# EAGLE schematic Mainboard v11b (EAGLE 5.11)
OC_FARNELL: 2019775

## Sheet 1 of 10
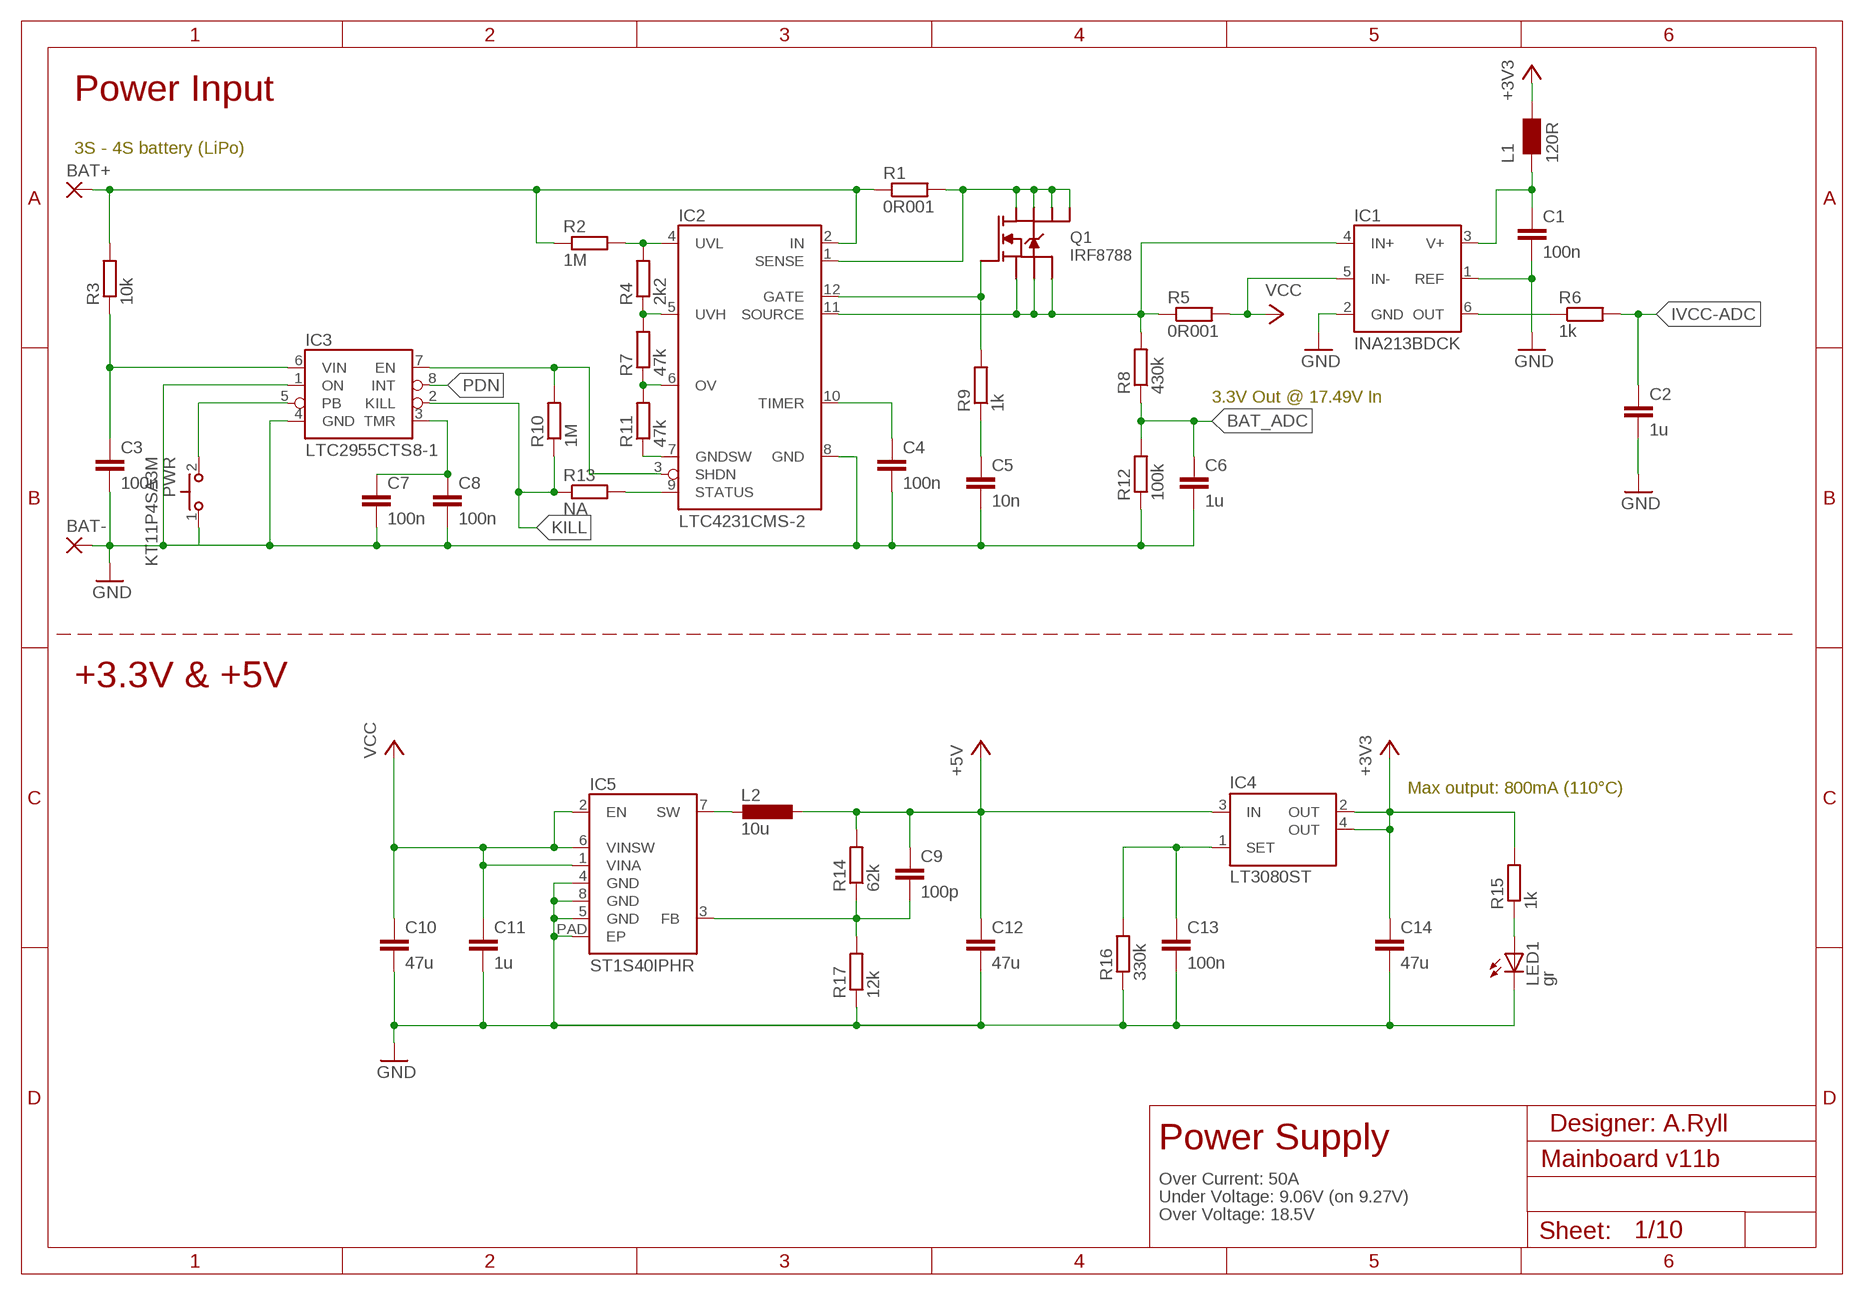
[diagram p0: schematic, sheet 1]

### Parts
BAT+  WIREPAD5,08/3  [5,08/3]
BAT-  WIREPAD5,08/3  [5,08/3]
C1  100n  C-EUC0603  [C0603]
C2  1u  C-EUC0603  [C0603]
C3  100n  C-EUC0603  [C0603]
C4  100n  C-EUC0603  [C0603]
C5  10n  C-EUC0603  [C0603]
C6  1u  C-EUC0603  [C0603]
C7  100n  C-EUC0603  [C0603]
C8  100n  C-EUC0603  [C0603]
C9  100p  C-EUC0603  [C0603]
C10  47u  C-EUC1210  [C1210]
C11  1u  C-EUC0603  [C0603]
C12  47u  C-EUC1210  [C1210]
C13  100n  C-EUC0603  [C0603]
C14  47u  C-EUC1210  [C1210]
IC1  INA213BDCK  INA21XDCK  [SC70-6L]
IC2  LTC4231CMS-2  LTC4231  [MSOP-12]
IC3  LTC2955CTS8-1  LTC2955  [SOT23-8]
IC4  LT3080ST  [SOT223]
IC5  ST1S40IPHR  [HSOP8]
L1  120R  WE-CBF_0603  [0603]
L2  10u  LHCI  [WE-HCI]
LED1  gr  LEDCHIP-LED0603  [CHIP-LED0603]
PWR  KT11P4SA3M  KT11  [KT11]
Q1  IRF8788  NMOS4D  [SOIC8]
R1  0R001  R-EU_R1206  [R1206]
R2  1M  R-EU_R0603  [R0603]
R3  10k  R-EU_R0603  [R0603]
R4  2k2  R-EU_R0603  [R0603]
R5  0R001  R-EU_R1206  [R1206]
R6  1k  R-EU_R0603  [R0603]
R7  47k  R-EU_R0603  [R0603]
R8  430k  R-EU_R0603  [R0603]
R9  1k  R-EU_R0603  [R0603]
R10  1M  R-EU_R0603  [R0603]
R11  47k  R-EU_R0603  [R0603]
R12  100k  R-EU_R0603  [R0603]
R13  NA  R-EU_R0603  [R0603]
R14  62k  R-EU_R0603  [R0603]
R15  1k  R-EU_R0603  [R0603]
R16  330k  R-EU_R0603  [R0603]
R17  12k  R-EU_R0603  [R0603]

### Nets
+3V3: C14.1 IC4.2(OUT) IC4.4(OUT) L1.2 R15.2 ; also sheet 2,3,4,5
+5V: C9.1 C12.1 IC4.3(IN) L2.1 R14.2 ; also sheet 2,3,5,6,7,8,9,10
BAT+: BAT+.P$1(P) IC2.2(IN) R1.1 R2.1 R3.2
BAT_ADC: C6.1 R8.1 R12.2 ; also sheet 2
FB2: C9.2 IC5.3(FB) R14.1 R17.2
GND: BAT-.P$1(P) C1.2 C2.2 C3.2 C4.2 C5.2 C6.2 C7.2 C8.2 C10.2 C11.2 C12.2 C13.2 C14.2 IC1.1(REF) IC1.2(GND) IC2.8(GND) IC3.1(ON) IC3.4(GND) IC5.4(GND) IC5.5(GND) IC5.8(GND) IC5.PAD(EP) LED1.C PWR.1 R12.1 R16.1 R17.1 ; also sheet 2,3,4,5,6,7,8,9,10
IVCC-ADC: C2.1 R6.2 ; also sheet 2
KILL: IC3.2(KILL) R10.1 R13.1 ; also sheet 5
M1-BIN+: IC2.1(SENSE) Q1.5(D1) Q1.6(D2) Q1.7(D3) Q1.8(D4) R1.2
N$6: C13.1 IC4.1(SET) R16.2
N$7: IC2.12(GATE) Q1.4(G) R9.2
N$10: IC2.4(UVL) R2.2 R4.2
N$11: IC2.6(OV) R7.1 R11.2
N$38: IC2.9(STATUS) R13.2
N$47: IC2.5(UVH) R4.1 R7.2
N$48: C5.1 R9.1
N$77: IC2.7(GNDSW) R11.1
N$78: IC2.3(SHDN) IC3.7(EN) R10.2
N$79: IC3.5(PB) PWR.2
N$81: C3.1 IC3.6(VIN) R3.1
N$82: C7.1 C8.1 IC3.3(TMR)
N$84: C4.1 IC2.10(TIMER)
N$107: IC1.6(OUT) R6.1
N$108: C1.1 IC1.3(V+) L1.1
N$120: LED1.A R15.1
PDN: IC3.8(INT) ; also sheet 5
SW2: IC5.7(SW) L2.2
VCC: C10.1 C11.1 IC1.5(IN-) IC5.1(VINA) IC5.2(EN) IC5.6(VINSW) R5.2 ; also sheet 2,3,6,7,8,9,10
VCC-SRC: IC1.4(IN+) IC2.11(SOURCE) Q1.1(S1) Q1.2(S2) Q1.3(S3) R5.1 R8.2

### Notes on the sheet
- Power Input
- 3S - 4S battery (LiPo)
- 3.3V Out @ 17.49V In
- +3.3V & +5V
- Max output: 800mA (110°C)
- Designer: A.Ryll
- Power Supply
- Over Current: 50A
- Under Voltage: 9.06V (on 9.27V)
- Over Voltage: 18.5V

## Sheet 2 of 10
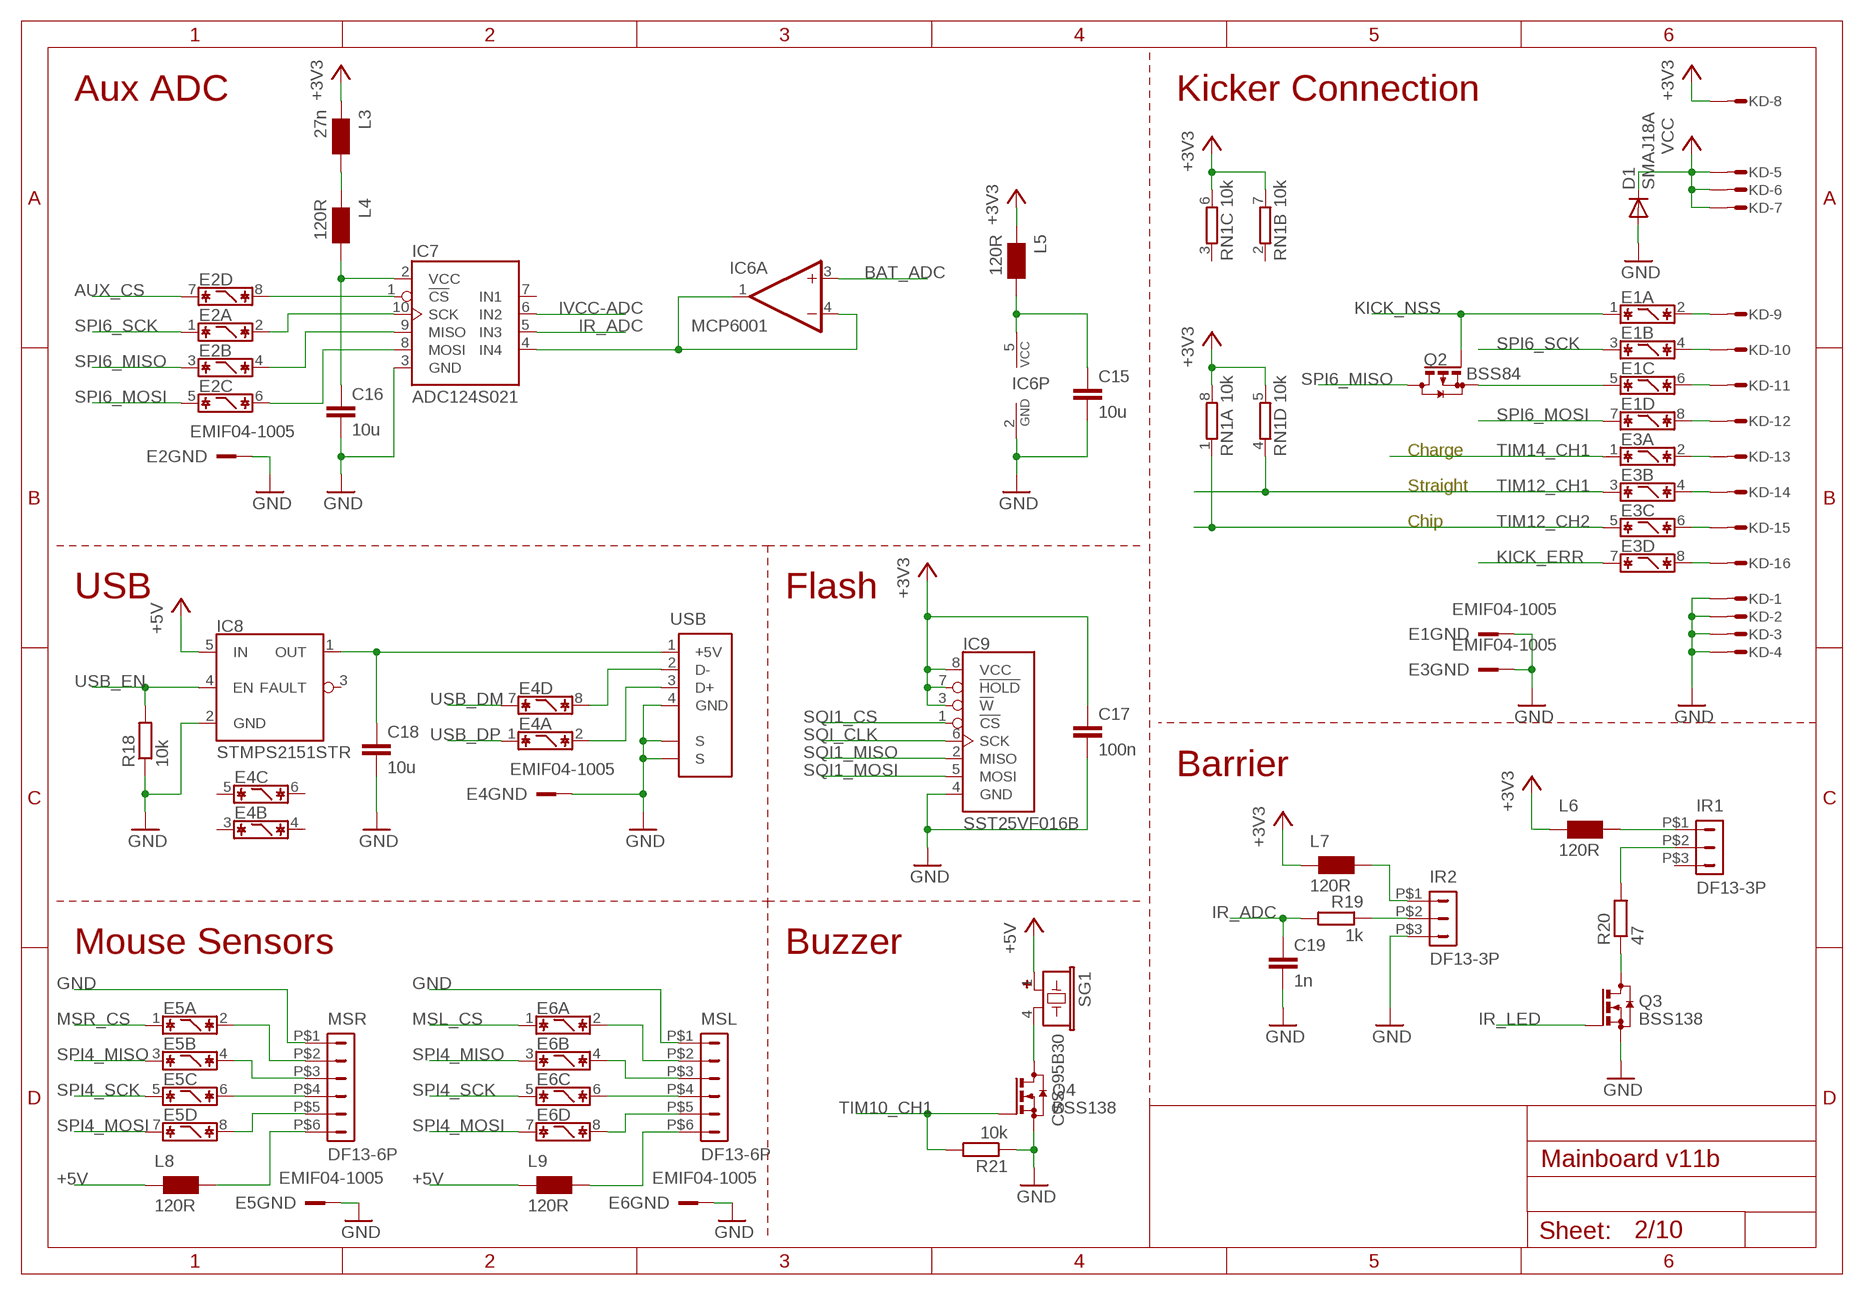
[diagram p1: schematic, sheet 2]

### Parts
C15  10u  C-EUC0603  [C0603]
C16  10u  C-EUC0603  [C0603]
C17  100n  C-EUC0603  [C0603]
C18  10u  C-EUC0603  [C0603]
C19  1n  C-EUC0603  [C0603]
D1  SMAJ18A  DIODE-DO214AC  [DO214AC]
E1  EMIF04-1005  [QFN17X15]
E2  EMIF04-1005  [QFN17X15]
E3  EMIF04-1005  [QFN17X15]
E4  EMIF04-1005  [QFN17X15]
E5  EMIF04-1005  [QFN17X15]
E6  EMIF04-1005  [QFN17X15]
IC6  MCP6001  AD-OP1RT  [SOT23-5]
IC7  ADC124S021  ADC__4S__1  [MSOP10-2]
IC8  STMPS2151STR  [SOT23-5]
IC9  SST25VF016B  FLASHB  [SO08-208]
IR1  DF13-3P  DF13-3P-1.25H  [DF13A-3P-1.25H]
IR2  DF13-3P  DF13-3P-1.25H  [DF13A-3P-1.25H]
KD  MICROMATCH-16SMF  [MMT-F-SMD-16]
L3  27n  WE-MI_0603  [0603]
L4  120R  WE-CBF_0603  [0603]
L5  120R  WE-CBF_0603  [0603]
L6  120R  WE-CBF_0603  [0603]
L7  120R  WE-CBF_0603  [0603]
L8  120R  WE-CBF_0603  [0603]
L9  120R  WE-CBF_0603  [0603]
MSL  DF13-6P  DF13-6P-1.25H  [DF13A-6P-1.25H]
MSR  DF13-6P  DF13-6P-1.25H  [DF13A-6P-1.25H]
Q2  BSS84  [SOT23]
Q3  BSS138  BSS123  [SOT23]
Q4  BSS138  BSS123  [SOT23]
R18  10k  R-EU_R0603  [R0603]
R19  1k  R-EU_R0603  [R0603]
R20  47  R-EU_R1206  [R1206]
R21  10k  R-EU_R0603  [R0603]
RN1  10k  4R-NEXB28V  [EXB28V]
SG1  CSS-95B30  BUZZER  [CSS-95B30]
USB  USBATE  [USBA-TE]

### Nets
+3V3: C17.1 IC9.3(!W) IC9.7(!HOLD) IC9.8(VCC) KD.8 L3.1 L5.1 L6.1 L7.1 RN1.5 RN1.6 RN1.7 RN1.8 ; also sheet 1,3,4,5
+5V: IC8.5(IN) L8.1 L9.1 SG1.1(+) ; also sheet 1,3,5,6,7,8,9,10
AUX_CS: E2.7 ; also sheet 5
BAT_ADC: IC6.3(A:+IN) ; also sheet 1
GND: C15.2 C16.2 C17.2 C18.2 C19.2 D1.A E1.GND(GND:KL) E2.GND(GND:KL) E3.GND(GND:KL) E4.GND(GND:KL) E5.GND(GND:KL) E6.GND(GND:KL) IC6.2(P:GND) IC7.3(GND) IC8.2(GND) IC9.4(GND) IR2.P$3 KD.1 KD.2 KD.3 KD.4 MSL.P$1 MSR.P$1 Q3.2(S) Q4.2(S) R18.1 R21.1 USB.4(GND) USB.MNT1(S) USB.MNT2(S) ; also sheet 1,3,4,5,6,7,8,9,10
IR_ADC: C19.1 IC7.5(IN3) R19.2
IR_LED: Q3.1(G) ; also sheet 5
IVCC-ADC: IC7.6(IN2) ; also sheet 1
KICK_ERR: E3.7 ; also sheet 5
KICK_NSS: E1.1 Q2.1(G) ; also sheet 5
MSL_CS: E6.1 ; also sheet 5
MSR_CS: E5.1 ; also sheet 5
N$3: IR2.P$2 R19.1
N$28: Q4.3(D) SG1.4(-)
N$43: L3.2 L4.1
N$45: IR2.P$1 L7.2
N$53: Q3.3(D) R20.1
N$54: IR1.P$2 R20.2
N$57: E5.2 MSR.P$2
N$63: E5.4 MSR.P$3
N$68: E5.6 MSR.P$4
N$69: C16.1 IC7.2(VCC) L4.2
N$70: E2.8 IC7.1(!CS)
N$71: E5.8 MSR.P$5
N$72: E2.2 IC7.10(SCK)
N$73: E2.6 IC7.8(MOSI)
N$74: E2.4 IC7.9(MISO)
N$75: IC6.1(A:OUT) IC6.4(A:-IN) IC7.4(IN4)
N$76: C15.1 IC6.5(P:VCC) L5.2
N$93: E4.8 USB.2(D-)
N$96: IR1.P$1 L6.2
N$101: E4.2 USB.3(D+)
N$104: E1.5 Q2.2(S)
N$111: L8.2 MSR.P$6
N$117: E6.2 MSL.P$2
N$136: E6.4 MSL.P$3
N$137: E6.6 MSL.P$4
N$138: E6.8 MSL.P$5
N$139: L9.2 MSL.P$6
N$192: E1.2 KD.9
N$201: E1.4 KD.10
N$202: E1.6 KD.11
N$203: E1.8 KD.12
N$204: E3.2 KD.13
N$205: E3.4 KD.14
N$206: E3.6 KD.15
N$214: E3.8 KD.16
SPI4_MISO: E5.3 E6.3 ; also sheet 3,5
SPI4_MOSI: E5.7 E6.7 ; also sheet 3,5
SPI4_SCK: E5.5 E6.5 ; also sheet 3,5
SPI6_MISO: E2.3 Q2.3(D) ; also sheet 3,5
SPI6_MOSI: E1.7 E2.5 ; also sheet 3,5
SPI6_SCK: E1.3 E2.1 ; also sheet 3,5
SQI1_CS: IC9.1(!CS) ; also sheet 5
SQI1_MISO: IC9.2(MISO) ; also sheet 5
SQI1_MOSI: IC9.5(MOSI) ; also sheet 5
SQI_CLK: IC9.6(SCK) ; also sheet 5
TIM10_CH1: Q4.1(G) R21.2 ; also sheet 5
TIM12_CH1: E3.3 RN1.4 ; also sheet 5
TIM12_CH2: E3.5 RN1.1 ; also sheet 5
TIM14_CH1: E3.1 ; also sheet 5
USB-5V: C18.1 IC8.1(OUT) USB.1(+5V)
USB_DM: E4.7 ; also sheet 5
USB_DP: E4.1 ; also sheet 5
USB_EN: IC8.4(EN) R18.2 ; also sheet 5
VCC: D1.C KD.5 KD.6 KD.7 ; also sheet 1,3,6,7,8,9,10
Unconnected: E4.3 E4.4 E4.5 E4.6 IC7.7(IN1) IC8.3(FAULT) IR1.P$3 RN1.2 RN1.3

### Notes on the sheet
- Aux ADC | Kicker Connection
- Charge
- Straight
- Chip
- USB | Flash
- Barrier
- Mouse Sensors | Buzzer

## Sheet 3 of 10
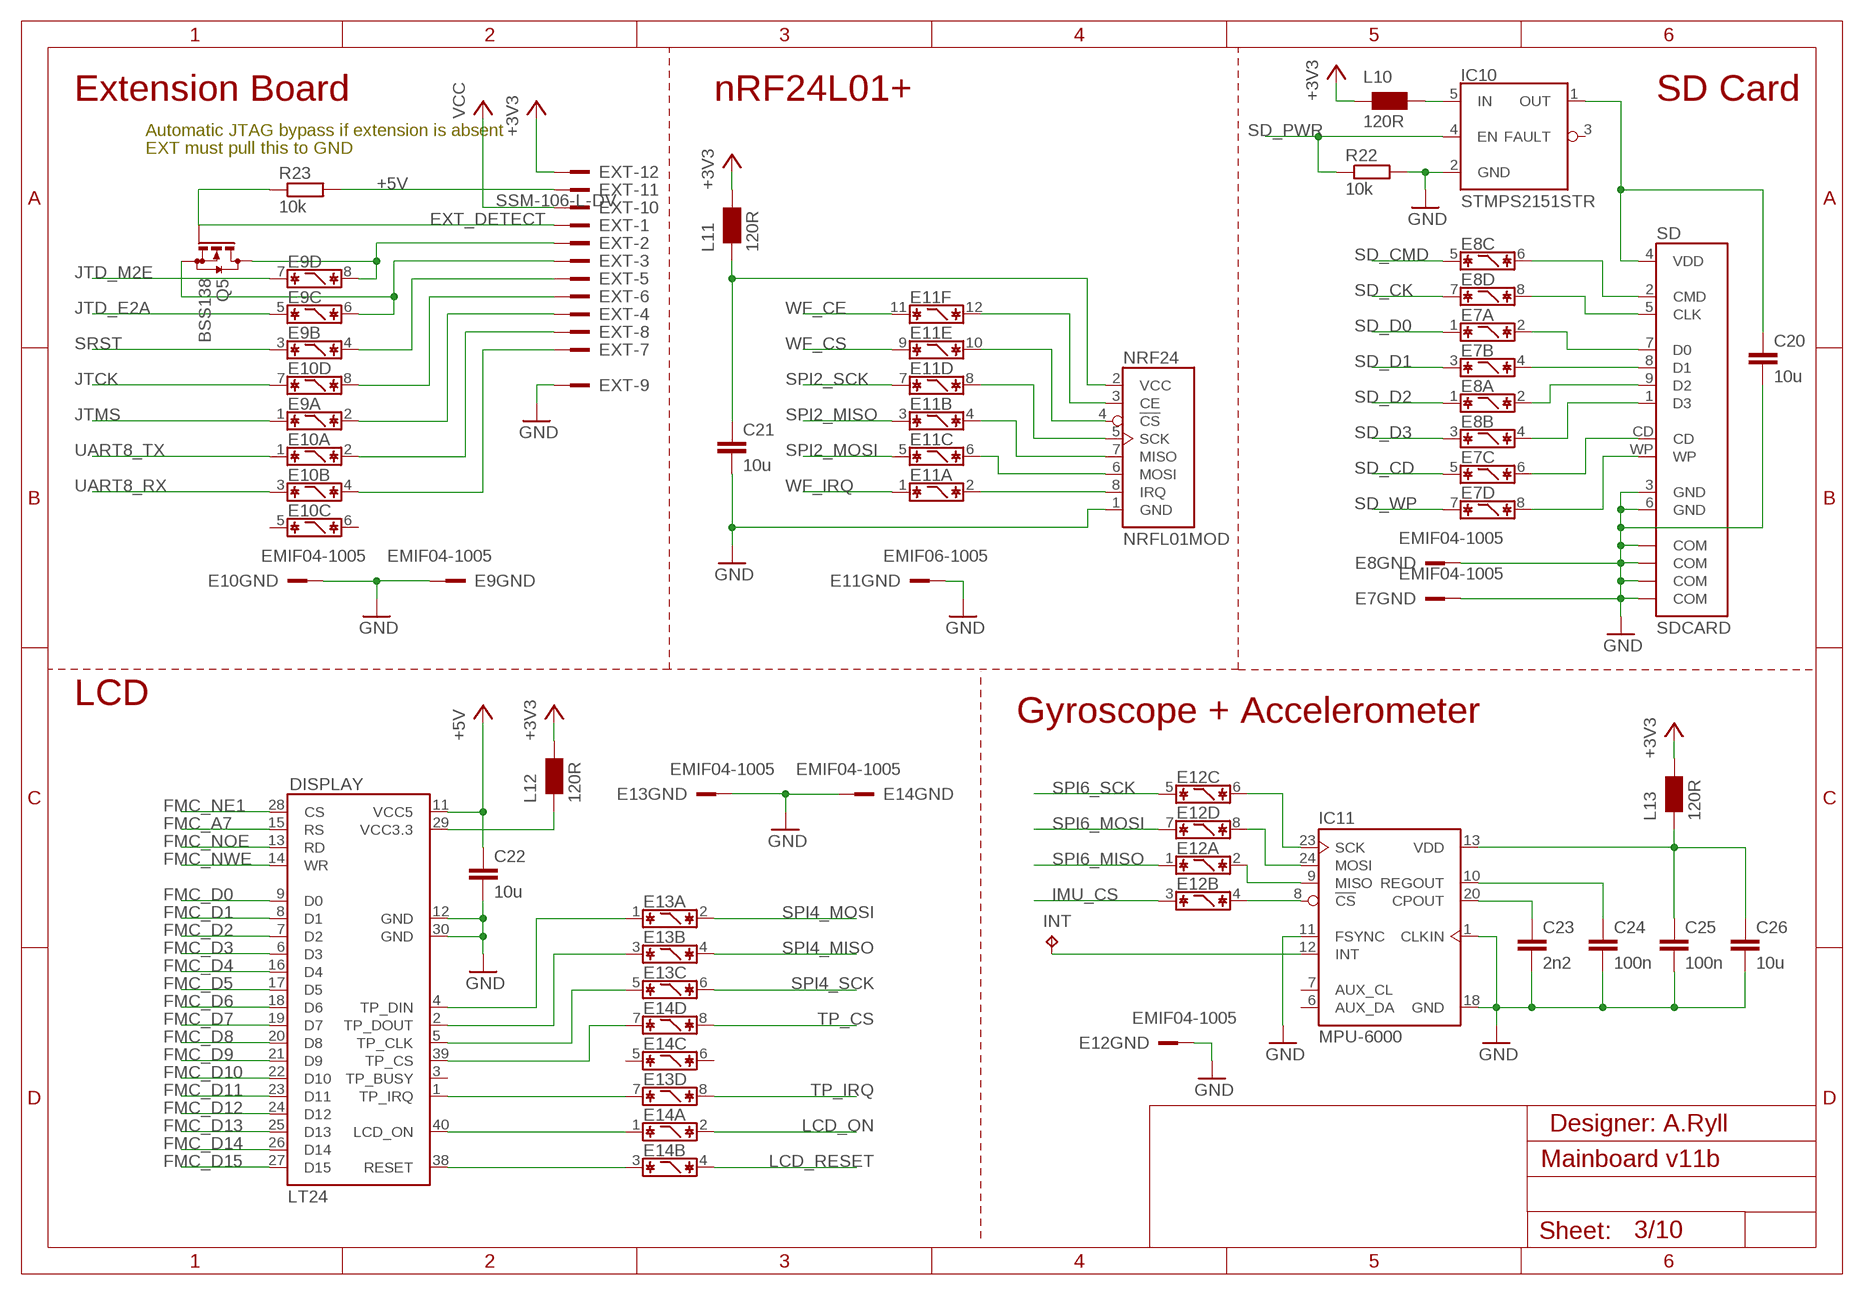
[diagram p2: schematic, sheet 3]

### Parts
C20  10u  C-EUC0603  [C0603]
C21  10u  C-EUC0603  [C0603]
C22  10u  C-EUC0603  [C0603]
C23  2n2  C-EUC0603  [C0603]
C24  100n  C-EUC0603  [C0603]
C25  100n  C-EUC0603  [C0603]
C26  10u  C-EUC0603  [C0603]
DISPLAY  LT24  [LT24]
E7  EMIF04-1005  [QFN17X15]
E8  EMIF04-1005  [QFN17X15]
E9  EMIF04-1005  [QFN17X15]
E10  EMIF04-1005  [QFN17X15]
E11  EMIF06-1005  [QFN25X15]
E12  EMIF04-1005  [QFN17X15]
E13  EMIF04-1005  [QFN17X15]
E14  EMIF04-1005  [QFN17X15]
EXT  SSM-106-L-DV  XSM-106-DV  [XSM-106-DV]
IC10  STMPS2151STR  [SOT23-5]
IC11  MPU-6000  [QFN4X4-24]
INT  TPTP08R  [TP08R]
L10  120R  WE-CBF_0603  [0603]
L11  120R  WE-CBF_0603  [0603]
L12  120R  WE-CBF_0603  [0603]
L13  120R  WE-CBF_0603  [0603]
NRF24  NRFL01MOD  NRFL01MODP  [NRF24L01SLR]
Q5  BSS138  BSS123  [SOT23]
R22  10k  R-EU_R0603  [R0603]
R23  10k  R-EU_R0603  [R0603]
SD  SDCARD  [SDCARD]

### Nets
+3V3: EXT.12 L10.1 L11.2 L12.2 L13.2 ; also sheet 1,2,4,5
+5V: C22.1 DISPLAY.11(VCC5) EXT.11 R23.2 ; also sheet 1,2,5,6,7,8,9,10
EXT_DETECT: EXT.1 Q5.1(G) R23.1
FMC_A7: DISPLAY.15(RS) ; also sheet 5
FMC_D0: DISPLAY.9(D0) ; also sheet 5
FMC_D1: DISPLAY.8(D1) ; also sheet 5
FMC_D2: DISPLAY.7(D2) ; also sheet 5
FMC_D3: DISPLAY.6(D3) ; also sheet 5
FMC_D4: DISPLAY.16(D4) ; also sheet 5
FMC_D5: DISPLAY.17(D5) ; also sheet 5
FMC_D6: DISPLAY.18(D6) ; also sheet 5
FMC_D7: DISPLAY.19(D7) ; also sheet 5
FMC_D8: DISPLAY.20(D8) ; also sheet 5
FMC_D9: DISPLAY.21(D9) ; also sheet 5
FMC_D10: DISPLAY.22(D10) ; also sheet 5
FMC_D11: DISPLAY.23(D11) ; also sheet 5
FMC_D12: DISPLAY.24(D12) ; also sheet 5
FMC_D13: DISPLAY.25(D13) ; also sheet 5
FMC_D14: DISPLAY.26(D14) ; also sheet 5
FMC_D15: DISPLAY.27(D15) ; also sheet 5
FMC_NE1: DISPLAY.28(CS) ; also sheet 5
FMC_NOE: DISPLAY.13(RD) ; also sheet 5
FMC_NWE: DISPLAY.14(WR) ; also sheet 5
GND: C20.2 C21.2 C22.2 C23.2 C24.2 C25.2 C26.2 DISPLAY.12(GND) DISPLAY.30(GND) E7.GND(GND:KL) E8.GND(GND:KL) E9.GND(GND:KL) E10.GND(GND:KL) E11.GND(GND:KL) E12.GND(GND:KL) E13.GND(GND:KL) E14.GND(GND:KL) EXT.9 IC10.2(GND) IC11.1(CLKIN) IC11.11(FSYNC) IC11.18(GND) NRF24.1(GND) R22.2 SD.3(GND) SD.6(GND) SD.COM1(COM) SD.COM2(COM) SD.COM3(COM) SD.COM4(COM) ; also sheet 1,2,4,5,6,7,8,9,10
IMU_CS: E12.3 ; also sheet 5
JTCK: E10.7 ; also sheet 4,5
JTD_E2A: E9.5 ; also sheet 4
JTD_M2E: E9.7 ; also sheet 5
JTMS: E9.1 ; also sheet 4,5
LCD_ON: E14.2 ; also sheet 5
LCD_RESET: E14.4 ; also sheet 5
N$1: IC10.5(IN) L10.2
N$4: C20.1 IC10.1(OUT) SD.4(VDD)
N$15: IC11.12(INT) INT.TP
N$17: E8.6 SD.2(CMD)
N$21: E8.8 SD.5(CLK)
N$23: E7.2 SD.7(D0)
N$24: E7.4 SD.8(D1)
N$26: C23.1 IC11.20(CPOUT)
N$27: C25.1 C26.1 IC11.13(VDD) L13.1
N$35: E8.2 SD.9(D2)
N$36: E8.4 SD.1(D3)
N$37: E7.6 SD.CD
N$39: E7.8 SD.WP
N$46: E9.8 EXT.2 Q5.3(D)
N$80: E9.6 EXT.3 Q5.2(S)
N$83: E9.4 EXT.5
N$85: E10.8 EXT.6
N$86: E9.2 EXT.4
N$87: E10.2 EXT.8
N$88: E10.4 EXT.7
N$95: DISPLAY.29(VCC3.3) L12.1
N$97: DISPLAY.4(TP_DIN) E13.1
N$98: DISPLAY.2(TP_DOUT) E13.3
N$99: DISPLAY.5(TP_CLK) E13.5
N$100: DISPLAY.39(TP_CS) E14.7
N$102: C21.1 L11.1 NRF24.2(VCC)
N$103: E11.2 NRF24.8(IRQ)
N$109: C24.1 IC11.10(REGOUT)
N$112: E11.4 NRF24.7(MISO)
N$113: E11.6 NRF24.6(MOSI)
N$114: E11.8 NRF24.5(SCK)
N$115: E11.10 NRF24.4(!CS)
N$116: E11.12 NRF24.3(CE)
N$118: E12.6 IC11.23(SCK)
N$119: E12.8 IC11.24(MOSI)
N$121: E12.2 IC11.9(MISO)
N$122: E12.4 IC11.8(!CS)
N$124: DISPLAY.1(TP_IRQ) E13.7
N$125: DISPLAY.40(LCD_ON) E14.1
N$126: DISPLAY.38(RESET) E14.3
SD_CD: E7.5 ; also sheet 5
SD_CK: E8.7 ; also sheet 5
SD_CMD: E8.5 ; also sheet 5
SD_D0: E7.1 ; also sheet 5
SD_D1: E7.3 ; also sheet 5
SD_D2: E8.1 ; also sheet 5
SD_D3: E8.3 ; also sheet 5
SD_PWR: IC10.4(EN) R22.1 ; also sheet 5
SD_WP: E7.7 ; also sheet 5
SPI2_MISO: E11.3 ; also sheet 5
SPI2_MOSI: E11.5 ; also sheet 5
SPI2_SCK: E11.7 ; also sheet 5
SPI4_MISO: E13.4 ; also sheet 2,5
SPI4_MOSI: E13.2 ; also sheet 2,5
SPI4_SCK: E13.6 ; also sheet 2,5
SPI6_MISO: E12.1 ; also sheet 2,5
SPI6_MOSI: E12.7 ; also sheet 2,5
SPI6_SCK: E12.5 ; also sheet 2,5
SRST: E9.3 ; also sheet 4,5
TP_CS: E14.8 ; also sheet 5
TP_IRQ: E13.8 ; also sheet 5
UART8_RX: E10.3 ; also sheet 5
UART8_TX: E10.1 ; also sheet 5
VCC: EXT.10 ; also sheet 1,2,6,7,8,9,10
WF_CE: E11.11 ; also sheet 5
WF_CS: E11.9 ; also sheet 5
WF_IRQ: E11.1 ; also sheet 5
Unconnected: DISPLAY.3(TP_BUSY) E10.5 E10.6 E14.5 E14.6 IC10.3(FAULT) IC11.6(AUX_DA) IC11.7(AUX_CL)

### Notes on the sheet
- Extension Board | nRF24L01+ | SD Card
- Automatic JTAG bypass if extension is absent
- EXT must pull this to GND
- LCD
- Gyroscope + Accelerometer
- Designer: A.Ryll

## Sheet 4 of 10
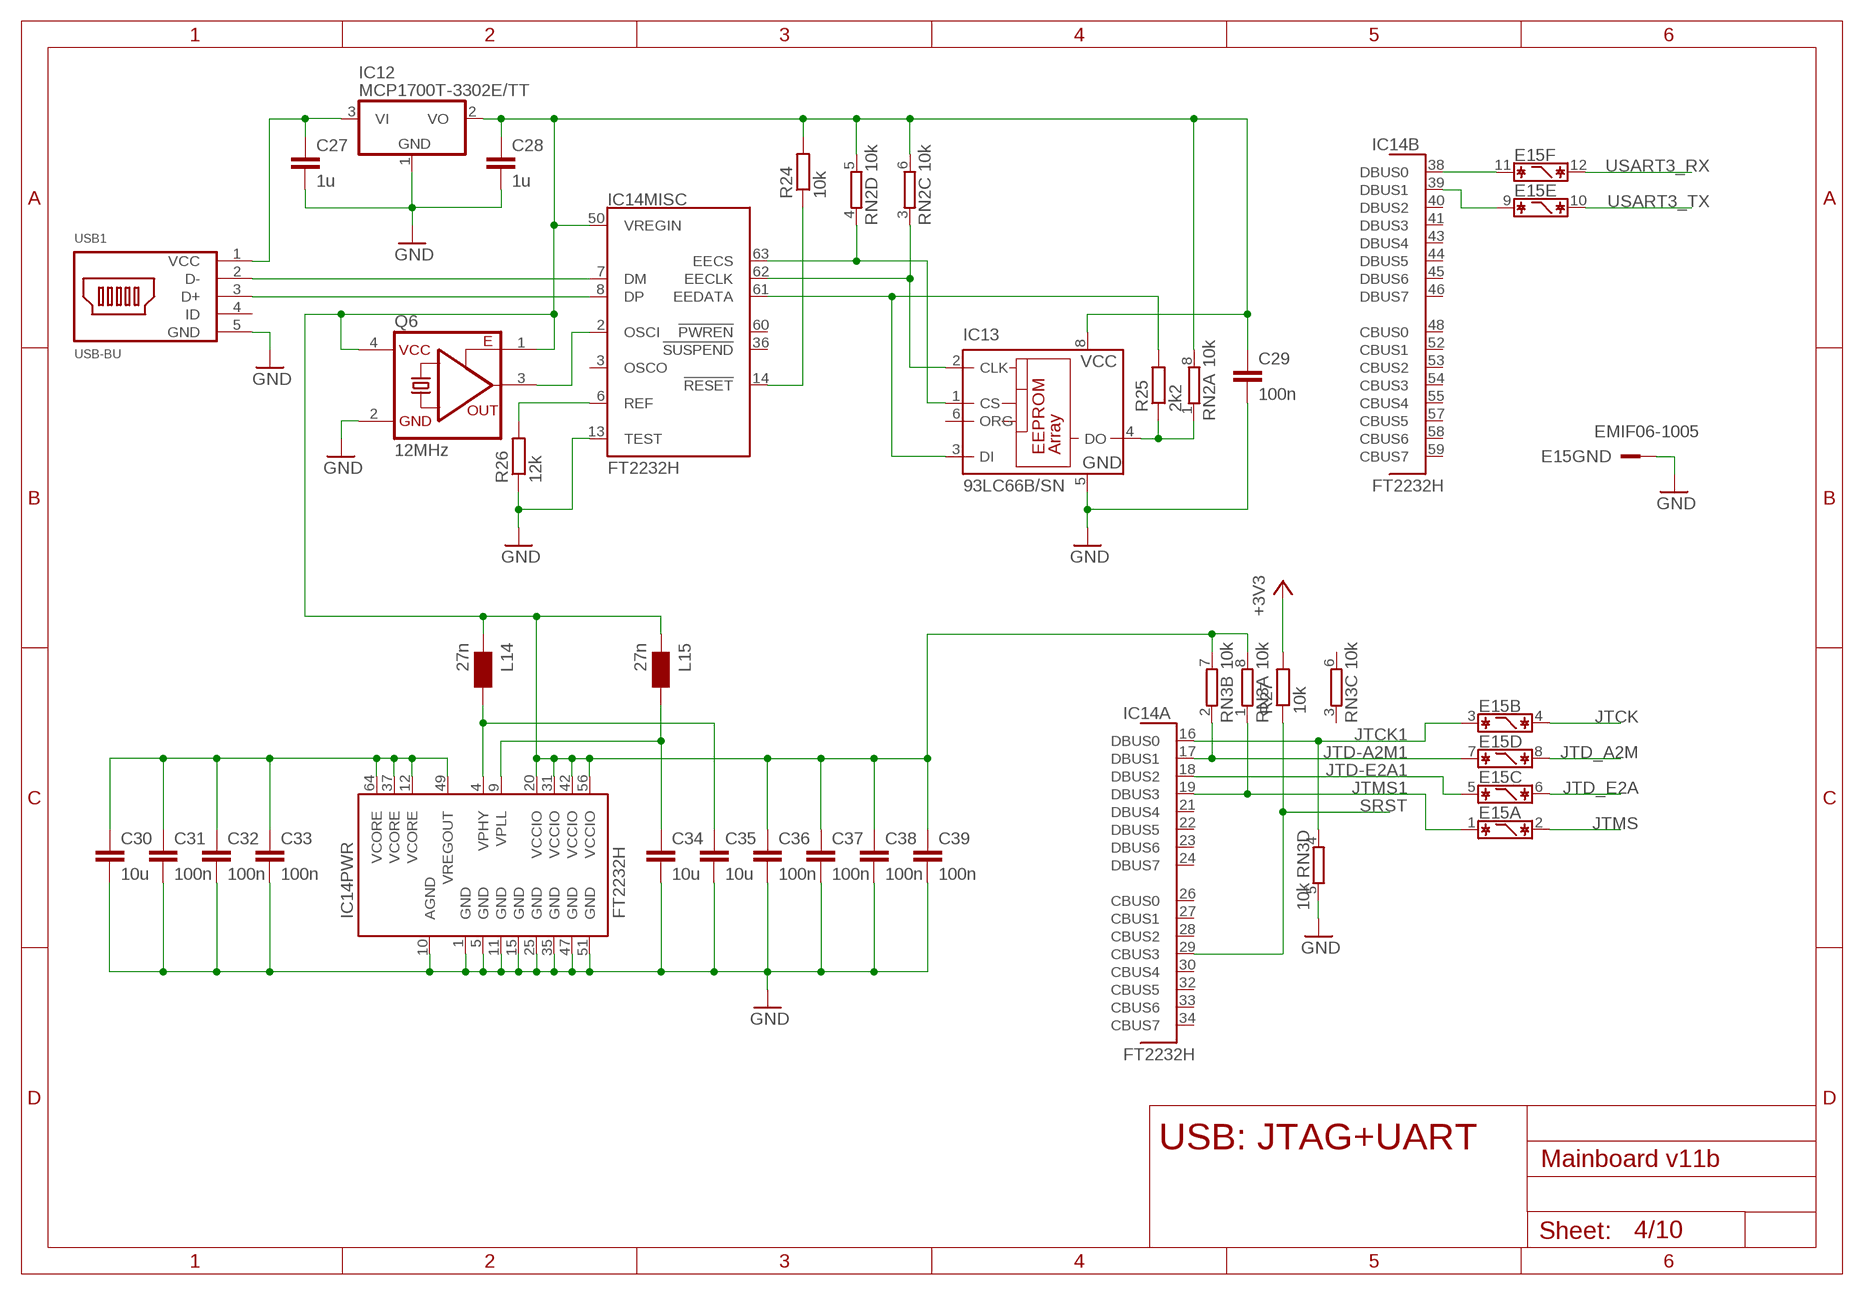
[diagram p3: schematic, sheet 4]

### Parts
C27  1u  C-EUC0603  [C0603]
C28  1u  C-EUC0603  [C0603]
C29  100n  C-EUC0603  [C0603]
C30  10u  C-EUC0603  [C0603]
C31  100n  C-EUC0603  [C0603]
C32  100n  C-EUC0603  [C0603]
C33  100n  C-EUC0603  [C0603]
C34  10u  C-EUC0603  [C0603]
C35  10u  C-EUC0603  [C0603]
C36  100n  C-EUC0603  [C0603]
C37  100n  C-EUC0603  [C0603]
C38  100n  C-EUC0603  [C0603]
C39  100n  C-EUC0603  [C0603]
E15  EMIF06-1005  [QFN25X15]
IC12  MCP1700T-3302E/TT  MCP1703CB  [SOT23]
IC13  93LC66B/SN  93LC66SN  [SO-08]
IC14  FT2232H  [LQFP64-ST]
L14  27n  WE-MI_0603  [0603]
L15  27n  WE-MI_0603  [0603]
Q6  12MHz  OSCI8W  [CRYSTAL-8W]
R24  10k  R-EU_R0603  [R0603]
R25  2k2  R-EU_R0603  [R0603]
R26  12k  R-EU_R0603  [R0603]
R27  10k  R-EU_R0603  [R0603]
RN2  10k  4R-NEXB28V  [EXB28V]
RN3  10k  4R-NEXB28V  [EXB28V]
USB1  USB-BU  [USB-BMICRO]

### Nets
+3V3: R27.2 ; also sheet 1,2,3,5
FT_3V3: C28.1 C29.1 C36.1 C37.1 C38.1 C39.1 IC12.2(VO) IC13.8(VCC) IC14.20(PWR:VCCIO) IC14.31(PWR:VCCIO) IC14.42(PWR:VCCIO) IC14.50(MISC:VREGIN) IC14.56(PWR:VCCIO) L14.1 L15.1 Q6.1(OE) Q6.4(VCC) R24.2 RN2.5 RN2.6 RN2.8 RN3.7 RN3.8
GND: C27.2 C28.2 C29.2 C30.2 C31.2 C32.2 C33.2 C34.2 C35.2 C36.2 C37.2 C38.2 C39.2 E15.GND(GND:KL) IC12.1(GND) IC13.5(GND) IC14.1(PWR:GND) IC14.5(PWR:GND) IC14.10(PWR:AGND) IC14.11(PWR:GND) IC14.13(MISC:TEST) IC14.15(PWR:GND) IC14.25(PWR:GND) IC14.35(PWR:GND) IC14.47(PWR:GND) IC14.51(PWR:GND) Q6.2(GND) R26.1 RN3.5 USB1.5(GND) ; also sheet 1,2,3,5,6,7,8,9,10
JTCK: E15.4 ; also sheet 3,5
JTCK1: E15.3 IC14.16(A:DBUS0) RN3.4
JTD-A2M1: E15.7 IC14.17(A:DBUS1) RN3.2
JTD-E2A1: E15.5 IC14.18(A:DBUS2)
JTD_A2M: E15.8 ; also sheet 5
JTD_E2A: E15.6 ; also sheet 3
JTMS: E15.2 ; also sheet 3,5
JTMS1: E15.1 IC14.19(A:DBUS3) RN3.1
N$41: C30.1 C31.1 C32.1 C33.1 IC14.12(PWR:VCORE) IC14.37(PWR:VCORE) IC14.49(PWR:VREGOUT) IC14.64(PWR:VCORE)
N$42: C27.1 IC12.3(VI) USB1.1(VCC)
N$44: IC14.7(MISC:DM) USB1.2(D-)
N$49: IC14.8(MISC:DP) USB1.3(D+)
N$51: IC14.6(MISC:REF) R26.2
N$52: C34.1 IC14.9(PWR:VPLL) L15.2
N$55: IC14.14(MISC:!RESET) R24.1
N$56: C35.1 IC14.4(PWR:VPHY) L14.2
N$58: IC14.2(MISC:OSCI) Q6.3(FO)
N$59: IC13.4(DO) R25.1 RN2.1
N$60: IC13.3(DI) IC14.61(MISC:EEDATA) R25.2
N$61: IC13.2(CLK) IC14.62(MISC:EECLK) RN2.3
N$62: IC13.1(CS) IC14.63(MISC:EECS) RN2.4
N$64: E15.11 IC14.38(B:DBUS0)
N$66: E15.9 IC14.39(B:DBUS1)
SRST: IC14.29(A:CBUS3) R27.1 ; also sheet 3,5
USART3_RX: E15.12 ; also sheet 5
USART3_TX: E15.10 ; also sheet 5
Unconnected: IC13.6(ORG) IC13.7(NU) IC14.3(MISC:OSCO) IC14.21(A:DBUS4) IC14.22(A:DBUS5) IC14.23(A:DBUS6) IC14.24(A:DBUS7) IC14.26(A:CBUS0) IC14.27(A:CBUS1) IC14.28(A:CBUS2) IC14.30(A:CBUS4) IC14.32(A:CBUS5) IC14.33(A:CBUS6) IC14.34(A:CBUS7) IC14.36(MISC:!SUSPEND) IC14.40(B:DBUS2) IC14.41(B:DBUS3) IC14.43(B:DBUS4) IC14.44(B:DBUS5) IC14.45(B:DBUS6) IC14.46(B:DBUS7) IC14.48(B:CBUS0) IC14.52(B:CBUS1) IC14.53(B:CBUS2) IC14.54(B:CBUS3) IC14.55(B:CBUS4) IC14.57(B:CBUS5) IC14.58(B:CBUS6) IC14.59(B:CBUS7) IC14.60(MISC:!PWREN) RN2.2 RN2.7 RN3.3 RN3.6 USB1.4(ID)

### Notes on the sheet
- USB: JTAG+UART

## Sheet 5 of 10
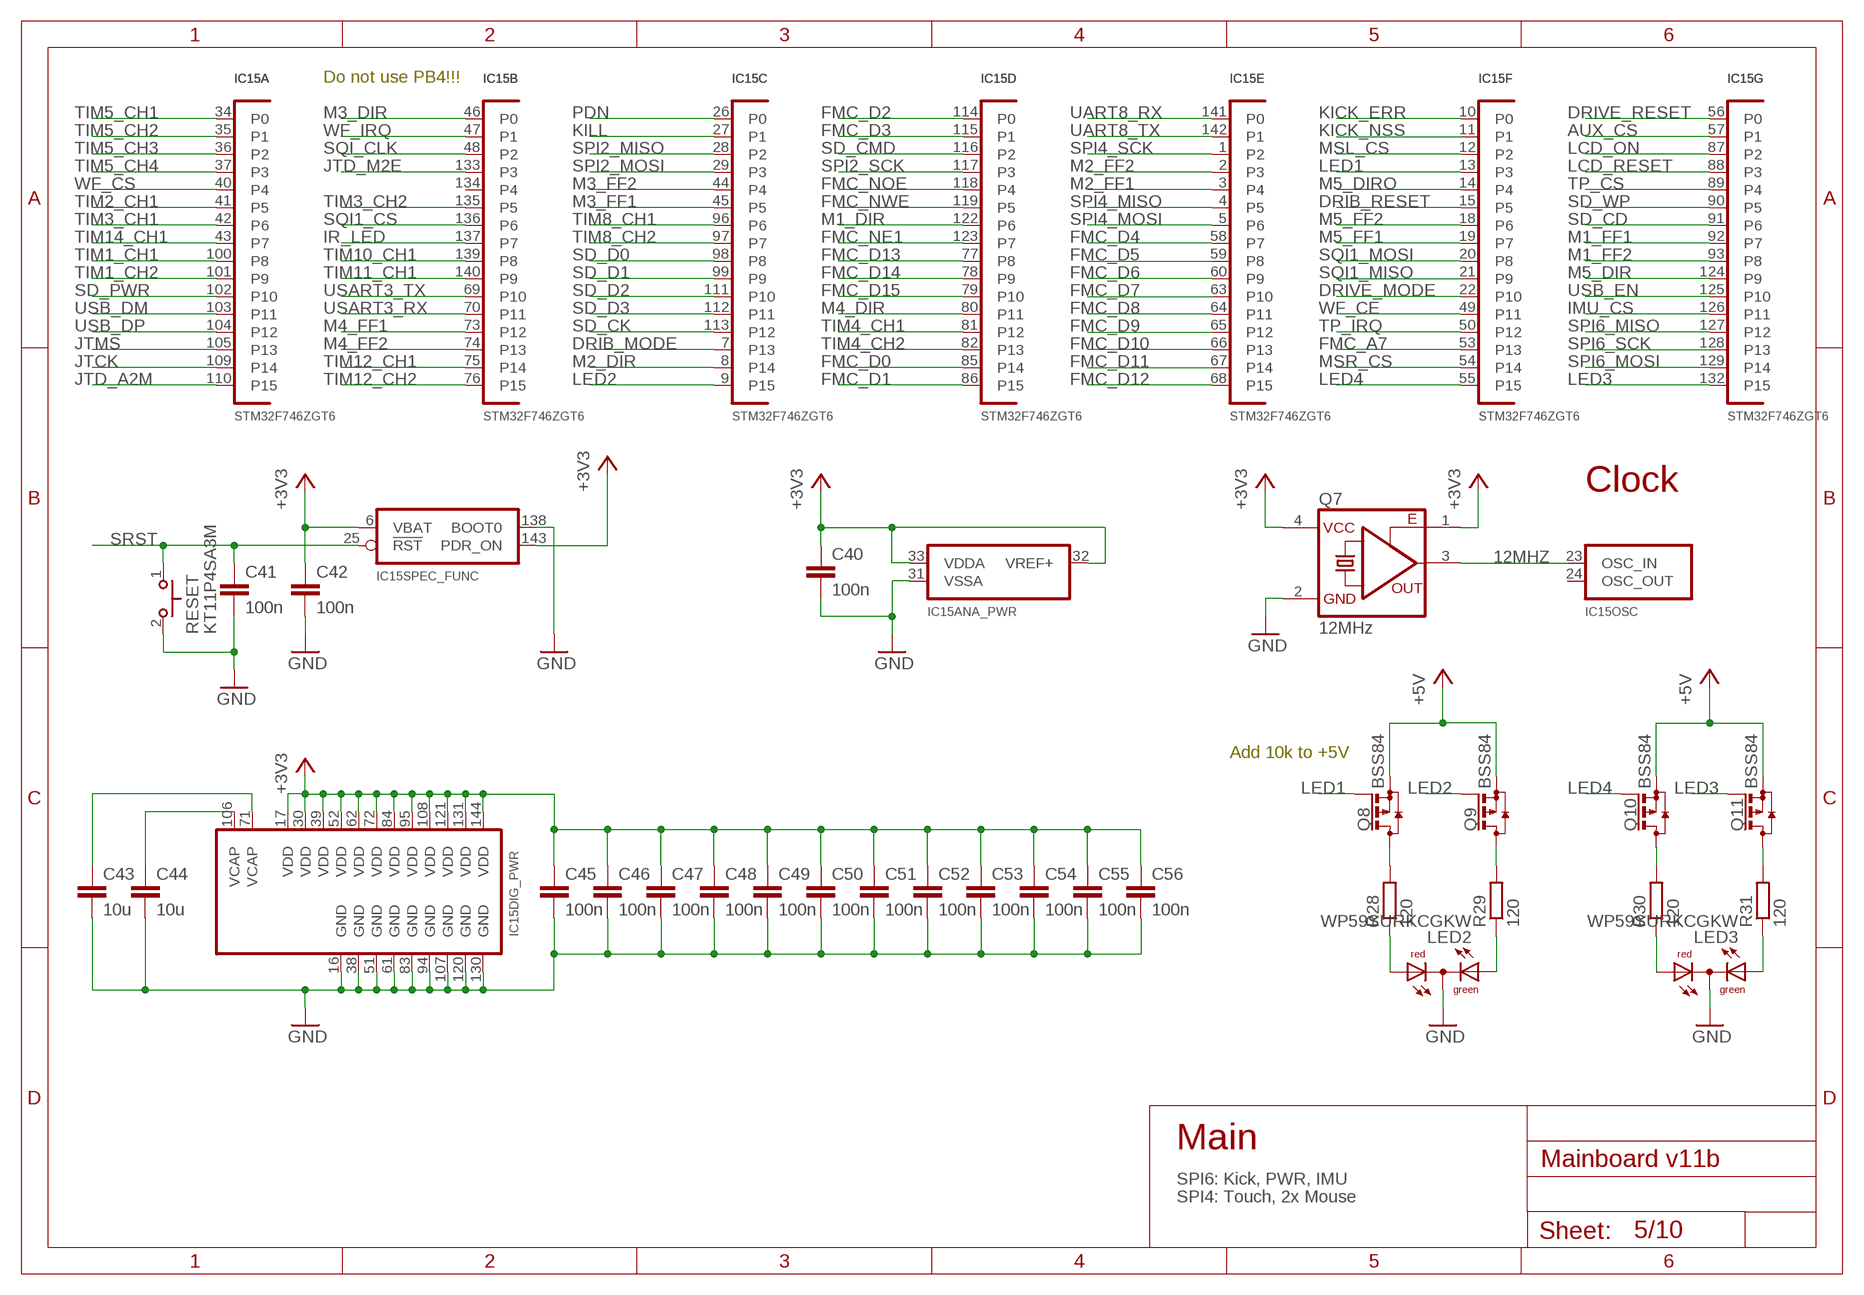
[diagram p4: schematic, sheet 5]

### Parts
C40  100n  C-EUC0603  [C0603]
C41  100n  C-EUC0603  [C0603]
C42  100n  C-EUC0603  [C0603]
C43  10u  C-EUC0603  [C0603]
C44  10u  C-EUC0603  [C0603]
C45  100n  C-EUC0603  [C0603]
C46  100n  C-EUC0603  [C0603]
C47  100n  C-EUC0603  [C0603]
C48  100n  C-EUC0603  [C0603]
C49  100n  C-EUC0603  [C0603]
C50  100n  C-EUC0603  [C0603]
C51  100n  C-EUC0603  [C0603]
C52  100n  C-EUC0603  [C0603]
C53  100n  C-EUC0603  [C0603]
C54  100n  C-EUC0603  [C0603]
C55  100n  C-EUC0603  [C0603]
C56  100n  C-EUC0603  [C0603]
IC15  STM32F746ZGT6  STM32F74_ZST  [LQFP144-ST]
LED2  WP59SURKCGKW  DUOLED5MM  [DUOLED5MM]
LED3  WP59SURKCGKW  DUOLED5MM  [DUOLED5MM]
Q7  12MHz  OSCI8W  [CRYSTAL-8W]
Q8  BSS84  [SOT23]
Q9  BSS84  [SOT23]
Q10  BSS84  [SOT23]
Q11  BSS84  [SOT23]
R28  120  R-EU_R1206  [R1206]
R29  120  R-EU_R1206  [R1206]
R30  120  R-EU_R1206  [R1206]
R31  120  R-EU_R1206  [R1206]
RESET  KT11P4SA3M  KT11  [KT11]

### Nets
12MHZ: IC15.23(OSC:OSC_IN) Q7.3(FO)
+3V3: C40.1 C42.1 C45.1 C46.1 C47.1 C48.1 C49.1 C50.1 C51.1 C52.1 C53.1 C54.1 C55.1 C56.1 IC15.6(SPEC_FUNC:VBAT) IC15.17(DIG_PWR:VDD) IC15.30(DIG_PWR:VDD) IC15.32(ANA_PWR:VREF+) IC15.33(ANA_PWR:VDDA) IC15.39(DIG_PWR:VDD) IC15.52(DIG_PWR:VDD) IC15.62(DIG_PWR:VDD) IC15.72(DIG_PWR:VDD) IC15.84(DIG_PWR:VDD) IC15.95(DIG_PWR:VDD) IC15.108(DIG_PWR:VDD) IC15.121(DIG_PWR:VDD) IC15.131(DIG_PWR:VDD) IC15.143(SPEC_FUNC:PDR_ON) IC15.144(DIG_PWR:VDD) Q7.1(OE) Q7.4(VCC) ; also sheet 1,2,3,4
+5V: Q8.2(S) Q9.2(S) Q10.2(S) Q11.2(S) ; also sheet 1,2,3,6,7,8,9,10
AUX_CS: IC15.57(G:P1) ; also sheet 2
DRIB_MODE: IC15.7(C:P13) ; also sheet 10
DRIB_RESET: IC15.15(F:P5) ; also sheet 10
DRIVE_MODE: IC15.22(F:P10) ; also sheet 6,7,8,9
DRIVE_RESET: IC15.56(G:P0) ; also sheet 6,7,8,9
FMC_A7: IC15.53(F:P13) ; also sheet 3
FMC_D0: IC15.85(D:P14) ; also sheet 3
FMC_D1: IC15.86(D:P15) ; also sheet 3
FMC_D2: IC15.114(D:P0) ; also sheet 3
FMC_D3: IC15.115(D:P1) ; also sheet 3
FMC_D4: IC15.58(E:P7) ; also sheet 3
FMC_D5: IC15.59(E:P8) ; also sheet 3
FMC_D6: IC15.60(E:P9) ; also sheet 3
FMC_D7: IC15.63(E:P10) ; also sheet 3
FMC_D8: IC15.64(E:P11) ; also sheet 3
FMC_D9: IC15.65(E:P12) ; also sheet 3
FMC_D10: IC15.66(E:P13) ; also sheet 3
FMC_D11: IC15.67(E:P14) ; also sheet 3
FMC_D12: IC15.68(E:P15) ; also sheet 3
FMC_D13: IC15.77(D:P8) ; also sheet 3
FMC_D14: IC15.78(D:P9) ; also sheet 3
FMC_D15: IC15.79(D:P10) ; also sheet 3
FMC_NE1: IC15.123(D:P7) ; also sheet 3
FMC_NOE: IC15.118(D:P4) ; also sheet 3
FMC_NWE: IC15.119(D:P5) ; also sheet 3
GND: C40.2 C41.2 C42.2 C43.2 C44.2 C45.2 C46.2 C47.2 C48.2 C49.2 C50.2 C51.2 C52.2 C53.2 C54.2 C55.2 C56.2 IC15.16(DIG_PWR:GND) IC15.31(ANA_PWR:VSSA) IC15.38(DIG_PWR:GND) IC15.51(DIG_PWR:GND) IC15.61(DIG_PWR:GND) IC15.83(DIG_PWR:GND) IC15.94(DIG_PWR:GND) IC15.107(DIG_PWR:GND) IC15.120(DIG_PWR:GND) IC15.130(DIG_PWR:GND) IC15.138(SPEC_FUNC:BOOT0) LED2.K(C) LED3.K(C) Q7.2(GND) RESET.2 ; also sheet 1,2,3,4,6,7,8,9,10
IMU_CS: IC15.126(G:P11) ; also sheet 3
IR_LED: IC15.137(B:P7) ; also sheet 2
JTCK: IC15.109(A:P14) ; also sheet 3,4
JTD_A2M: IC15.110(A:P15) ; also sheet 4
JTD_M2E: IC15.133(B:P3) ; also sheet 3
JTMS: IC15.105(A:P13) ; also sheet 3,4
KICK_ERR: IC15.10(F:P0) ; also sheet 2
KICK_NSS: IC15.11(F:P1) ; also sheet 2
KILL: IC15.27(C:P1) ; also sheet 1
LCD_ON: IC15.87(G:P2) ; also sheet 3
LCD_RESET: IC15.88(G:P3) ; also sheet 3
LED1: IC15.13(F:P3) Q8.1(G)
LED2: IC15.9(C:P15) Q9.1(G)
LED3: IC15.132(G:P15) Q11.1(G)
LED4: IC15.55(F:P15) Q10.1(G)
M1_DIR: IC15.122(D:P6) ; also sheet 6
M1_FF1: IC15.92(G:P7) ; also sheet 6
M1_FF2: IC15.93(G:P8) ; also sheet 6
M2_DIR: IC15.8(C:P14) ; also sheet 7
M2_FF1: IC15.3(E:P4) ; also sheet 7
M2_FF2: IC15.2(E:P3) ; also sheet 7
M3_DIR: IC15.46(B:P0) ; also sheet 8
M3_FF1: IC15.45(C:P5) ; also sheet 8
M3_FF2: IC15.44(C:P4) ; also sheet 8
M4_DIR: IC15.80(D:P11) ; also sheet 9
M4_FF1: IC15.73(B:P12) ; also sheet 9
M4_FF2: IC15.74(B:P13) ; also sheet 9
M5_DIR: IC15.124(G:P9) ; also sheet 10
M5_DIRO: IC15.14(F:P4) ; also sheet 10
M5_FF1: IC15.19(F:P7) ; also sheet 10
M5_FF2: IC15.18(F:P6) ; also sheet 10
MSL_CS: IC15.12(F:P2) ; also sheet 2
MSR_CS: IC15.54(F:P14) ; also sheet 2
N$19: C44.1 IC15.106(DIG_PWR:VCAP)
N$25: LED2.AG R29.1
N$31: C43.1 IC15.71(DIG_PWR:VCAP)
N$40: Q9.3(D) R29.2
N$110: LED2.AR R28.1
N$123: LED3.AG R31.1
N$135: LED3.AR R30.1
N$140: Q8.3(D) R28.2
N$146: Q10.3(D) R30.2
N$147: Q11.3(D) R31.2
PDN: IC15.26(C:P0) ; also sheet 1
SD_CD: IC15.91(G:P6) ; also sheet 3
SD_CK: IC15.113(C:P12) ; also sheet 3
SD_CMD: IC15.116(D:P2) ; also sheet 3
SD_D0: IC15.98(C:P8) ; also sheet 3
SD_D1: IC15.99(C:P9) ; also sheet 3
SD_D2: IC15.111(C:P10) ; also sheet 3
SD_D3: IC15.112(C:P11) ; also sheet 3
SD_PWR: IC15.102(A:P10) ; also sheet 3
SD_WP: IC15.90(G:P5) ; also sheet 3
SPI2_MISO: IC15.28(C:P2) ; also sheet 3
SPI2_MOSI: IC15.29(C:P3) ; also sheet 3
SPI2_SCK: IC15.117(D:P3) ; also sheet 3
SPI4_MISO: IC15.4(E:P5) ; also sheet 2,3
SPI4_MOSI: IC15.5(E:P6) ; also sheet 2,3
SPI4_SCK: IC15.1(E:P2) ; also sheet 2,3
SPI6_MISO: IC15.127(G:P12) ; also sheet 2,3
SPI6_MOSI: IC15.129(G:P14) ; also sheet 2,3
SPI6_SCK: IC15.128(G:P13) ; also sheet 2,3
SQI1_CS: IC15.136(B:P6) ; also sheet 2
SQI1_MISO: IC15.21(F:P9) ; also sheet 2
SQI1_MOSI: IC15.20(F:P8) ; also sheet 2
SQI_CLK: IC15.48(B:P2) ; also sheet 2
SRST: C41.1 IC15.25(SPEC_FUNC:!RST) RESET.1 ; also sheet 3,4
TIM1_CH1: IC15.100(A:P8) ; also sheet 6
TIM1_CH2: IC15.101(A:P9) ; also sheet 6
TIM2_CH1: IC15.41(A:P5) ; also sheet 10
TIM3_CH1: IC15.42(A:P6) ; also sheet 7
TIM3_CH2: IC15.135(B:P5) ; also sheet 7
TIM4_CH1: IC15.81(D:P12) ; also sheet 8
TIM4_CH2: IC15.82(D:P13) ; also sheet 8
TIM5_CH1: IC15.34(A:P0) ; also sheet 7
TIM5_CH2: IC15.35(A:P1) ; also sheet 6
TIM5_CH3: IC15.36(A:P2) ; also sheet 8
TIM5_CH4: IC15.37(A:P3) ; also sheet 9
TIM8_CH1: IC15.96(C:P6) ; also sheet 9
TIM8_CH2: IC15.97(C:P7) ; also sheet 9
TIM10_CH1: IC15.139(B:P8) ; also sheet 2
TIM11_CH1: IC15.140(B:P9) ; also sheet 10
TIM12_CH1: IC15.75(B:P14) ; also sheet 2
TIM12_CH2: IC15.76(B:P15) ; also sheet 2
TIM14_CH1: IC15.43(A:P7) ; also sheet 2
TP_CS: IC15.89(G:P4) ; also sheet 3
TP_IRQ: IC15.50(F:P12) ; also sheet 3
UART8_RX: IC15.141(E:P0) ; also sheet 3
UART8_TX: IC15.142(E:P1) ; also sheet 3
USART3_RX: IC15.70(B:P11) ; also sheet 4
USART3_TX: IC15.69(B:P10) ; also sheet 4
USB_DM: IC15.103(A:P11) ; also sheet 2
USB_DP: IC15.104(A:P12) ; also sheet 2
USB_EN: IC15.125(G:P10) ; also sheet 2
WF_CE: IC15.49(F:P11) ; also sheet 3
WF_CS: IC15.40(A:P4) ; also sheet 3
WF_IRQ: IC15.47(B:P1) ; also sheet 3
Unconnected: IC15.24(OSC:OSC_OUT) IC15.134(B:P4)

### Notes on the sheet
- Do not use PB4!!!
- Clock
- Add 10k to +5V
- Main
- SPI6: Kick, PWR, IMU
- SPI4: Touch, 2x Mouse

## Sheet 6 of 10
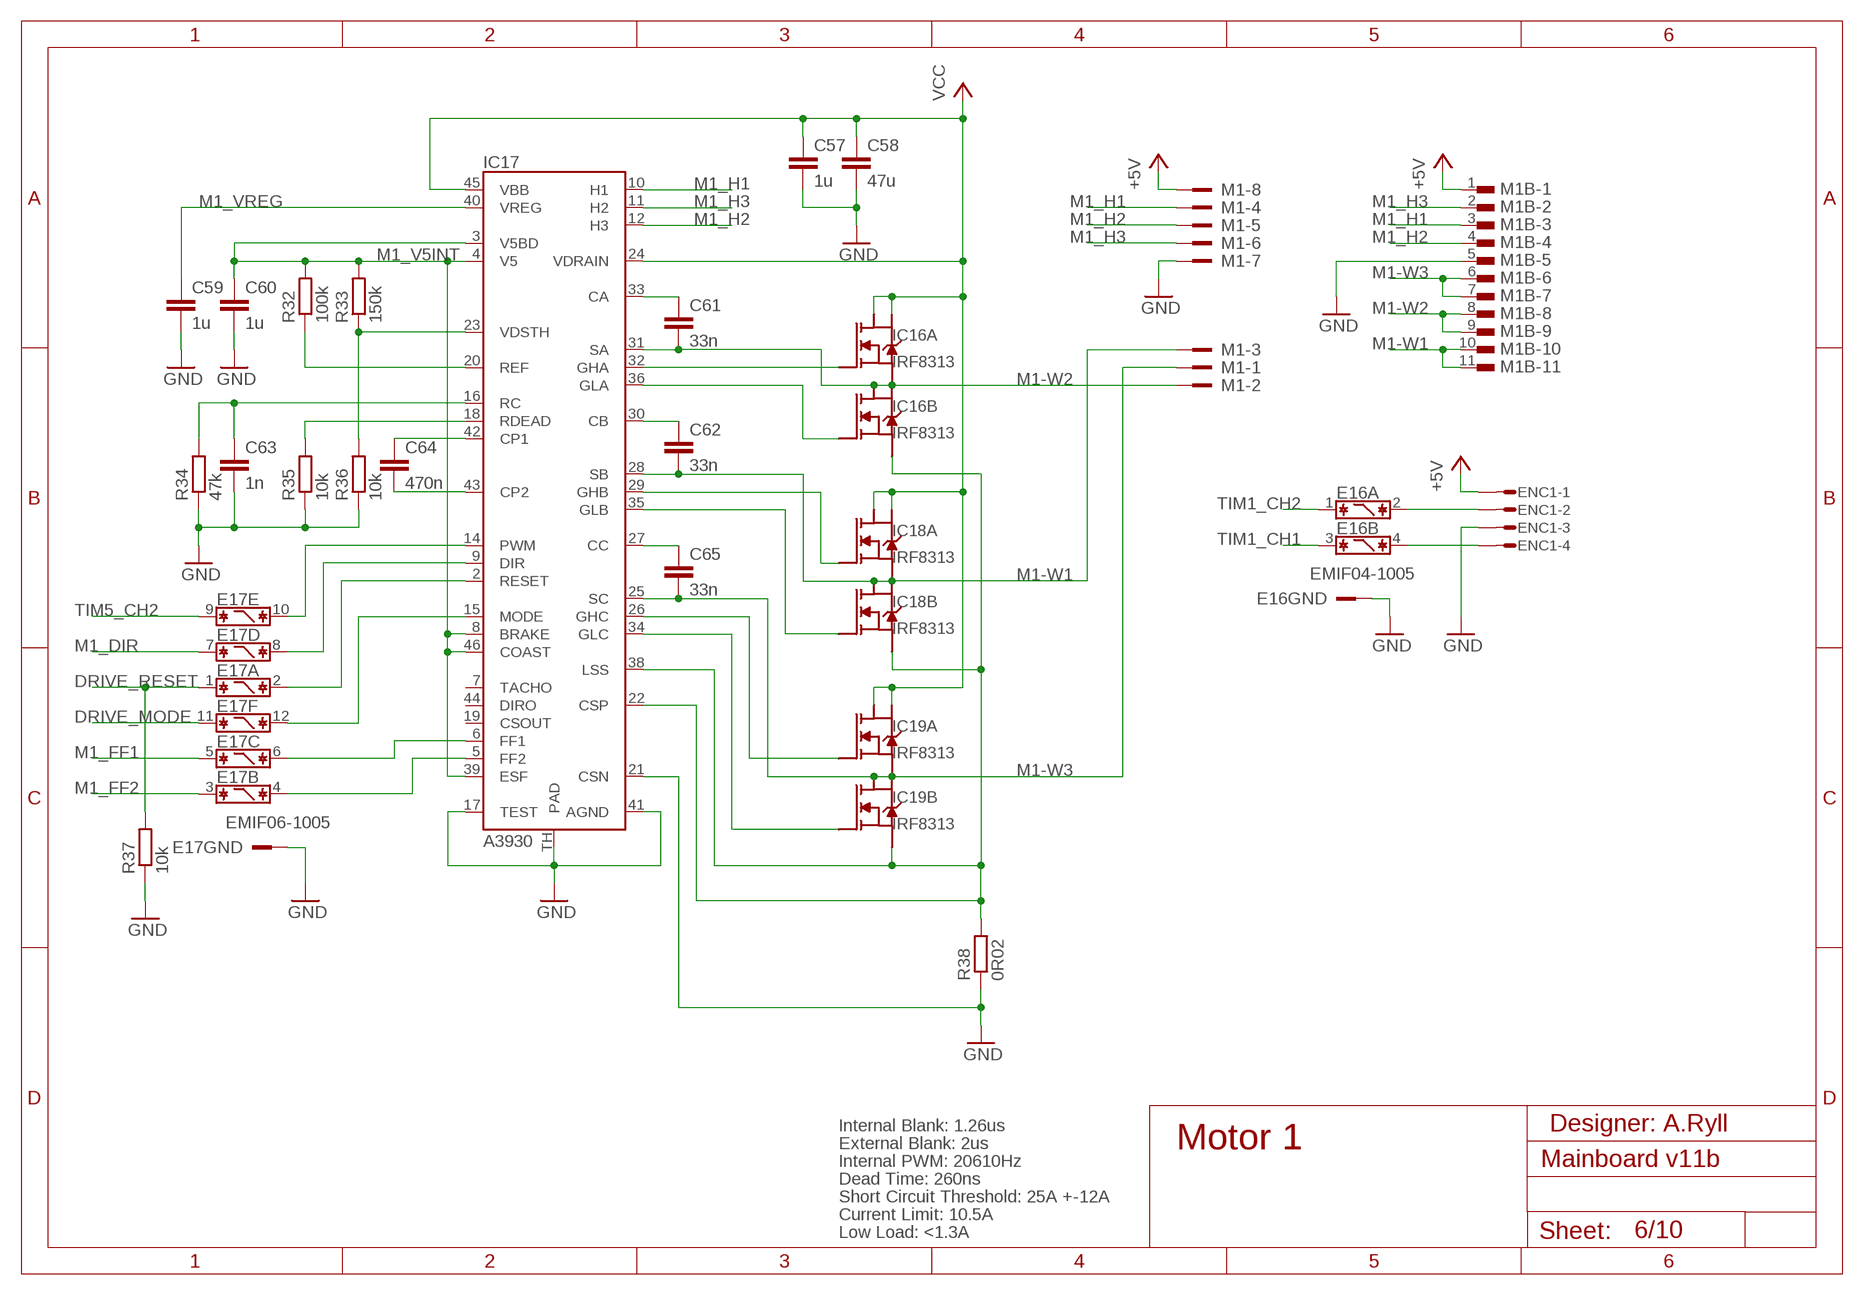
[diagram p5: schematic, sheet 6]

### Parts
C57  1u  C-EUC0603  [C0603]
C58  47u  C-EUC1210  [C1210]
C59  1u  C-EUC0603  [C0603]
C60  1u  C-EUC0603  [C0603]
C61  33n  C-EUC0603  [C0603]
C62  33n  C-EUC0603  [C0603]
C63  1n  C-EUC0603  [C0603]
C64  470n  C-EUC0603  [C0603]
C65  33n  C-EUC0603  [C0603]
E16  EMIF04-1005  [QFN17X15]
E17  EMIF06-1005  [QFN25X15]
ENC1  MICROMATCH-4SMF  [MMT-F-SMD-4]
IC16  IRF8313  IRF7103  [SOIC8]
IC17  A3930  A393X  [LQFP48-AL]
IC18  IRF8313  IRF7103  [SOIC8]
IC19  IRF8313  IRF7103  [SOIC8]
M1  XSM-108-SV  [XSM-108-SV]
M1B  MOLEX11B  [MOLEX11]
R32  100k  R-EU_R0603  [R0603]
R33  150k  R-EU_R0603  [R0603]
R34  47k  R-EU_R0603  [R0603]
R35  10k  R-EU_R0603  [R0603]
R36  10k  R-EU_R0603  [R0603]
R37  10k  R-EU_R0603  [R0603]
R38  0R02  R-EU_R1206  [R1206]

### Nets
+5V: ENC1.1 M1.8 M1B.1 ; also sheet 1,2,3,5,7,8,9,10
DRIVE_MODE: E17.11 ; also sheet 5,7,8,9
DRIVE_RESET: E17.1 R37.2 ; also sheet 5,7,8,9
GND: C57.2 C58.2 C59.2 C60.2 C63.2 E16.GND(GND:KL) E17.GND(GND:KL) ENC1.3 IC17.17(TEST) IC17.21(CSN) IC17.41(AGND) IC17.TH(PAD) M1.7 M1B.5 R34.1 R35.1 R36.1 R37.1 R38.1 ; also sheet 1,2,3,4,5,7,8,9,10
M1-COM: IC16.3(B:S) IC17.22(CSP) IC17.38(LSS) IC18.3(B:S) IC19.3(B:S) R38.2
M1-HO1: IC16.2(A:G) IC17.32(GHA)
M1-HO2: IC17.29(GHB) IC18.2(A:G)
M1-HO3: IC17.26(GHC) IC19.2(A:G)
M1-LO1: IC16.4(B:G) IC17.36(GLA)
M1-LO2: IC17.35(GLB) IC18.4(B:G)
M1-LO3: IC17.34(GLC) IC19.4(B:G)
M1-VB1: C61.1 IC17.33(CA)
M1-VB2: C62.1 IC17.30(CB)
M1-VB3: C65.1 IC17.27(CC)
M1-W1: C62.2 IC17.28(SB) IC18.1(A:S) IC18.5(B:D2) IC18.6(B:D1) M1.3 M1B.10 M1B.11
M1-W2: C61.2 IC16.1(A:S) IC16.5(B:D2) IC16.6(B:D1) IC17.31(SA) M1.2 M1B.8 M1B.9
M1-W3: C65.2 IC17.25(SC) IC19.1(A:S) IC19.5(B:D2) IC19.6(B:D1) M1.1 M1B.6 M1B.7
M1_DIR: E17.7 ; also sheet 5
M1_FF1: E17.5 ; also sheet 5
M1_FF2: E17.3 ; also sheet 5
M1_H1: IC17.10(H1) M1.4 M1B.3
M1_H2: IC17.12(H3) M1.5 M1B.4
M1_H3: IC17.11(H2) M1.6 M1B.2
M1_V5INT: C60.1 IC17.3(V5BD) IC17.4(V5) IC17.8(BRAKE) IC17.39(ESF) IC17.46(COAST) R32.2 R33.2
M1_VREG: C59.1 IC17.40(VREG)
N$14: E16.4 ENC1.4
N$16: E16.2 ENC1.2
N$20: C64.1 IC17.42(CP1)
N$22: C64.2 IC17.43(CP2)
N$29: IC17.18(RDEAD) R35.2
N$30: C63.1 IC17.16(RC) R34.2
N$32: IC17.20(REF) R32.1
N$33: IC17.23(VDSTH) R33.1 R36.2
N$65: E17.4 IC17.5(FF2)
N$67: E17.6 IC17.6(FF1)
N$90: E17.10 IC17.14(PWM)
N$91: E17.8 IC17.9(DIR)
N$92: E17.2 IC17.2(RESET)
N$106: E17.12 IC17.15(MODE)
TIM1_CH1: E16.3 ; also sheet 5
TIM1_CH2: E16.1 ; also sheet 5
TIM5_CH2: E17.9 ; also sheet 5
VCC: C57.1 C58.1 IC16.7(A:D2) IC16.8(A:D1) IC17.24(VDRAIN) IC17.45(VBB) IC18.7(A:D2) IC18.8(A:D1) IC19.7(A:D2) IC19.8(A:D1) ; also sheet 1,2,3,7,8,9,10
Unconnected: IC17.7(TACHO) IC17.19(CSOUT) IC17.44(DIRO)

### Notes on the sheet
- Internal Blank: 1.26us | Designer: A.Ryll
- External Blank: 2us | Motor 1
- Internal PWM: 20610Hz
- Dead Time: 260ns
- Short Circuit Threshold: 25A +-12A
- Current Limit: 10.5A
- Low Load: <1.3A

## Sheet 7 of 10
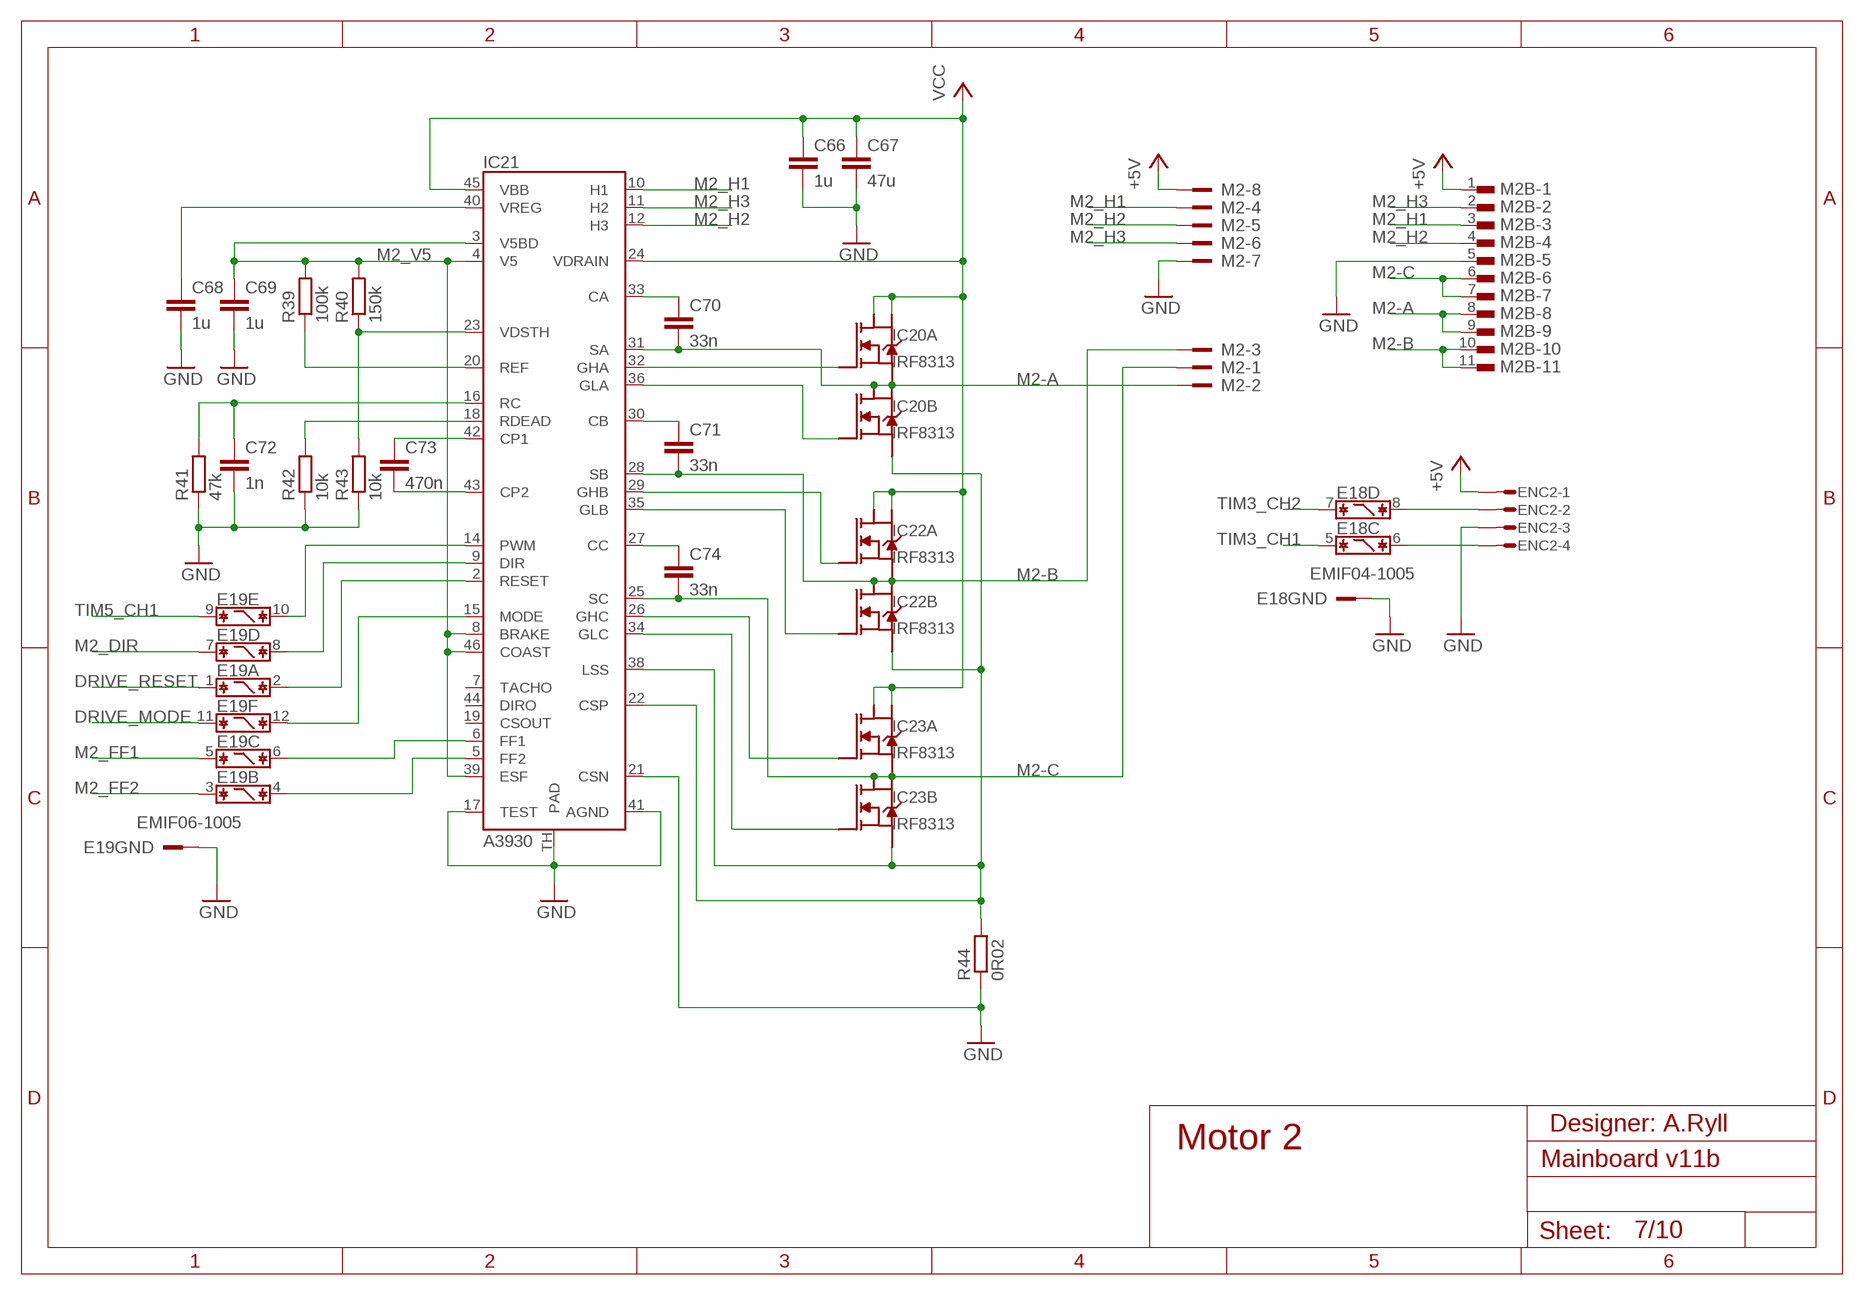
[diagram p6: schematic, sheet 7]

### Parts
C66  1u  C-EUC0603  [C0603]
C67  47u  C-EUC1210  [C1210]
C68  1u  C-EUC0603  [C0603]
C69  1u  C-EUC0603  [C0603]
C70  33n  C-EUC0603  [C0603]
C71  33n  C-EUC0603  [C0603]
C72  1n  C-EUC0603  [C0603]
C73  470n  C-EUC0603  [C0603]
C74  33n  C-EUC0603  [C0603]
E18  EMIF04-1005  [QFN17X15]
E19  EMIF06-1005  [QFN25X15]
ENC2  MICROMATCH-4SMF  [MMT-F-SMD-4]
IC20  IRF8313  IRF7103  [SOIC8]
IC21  A3930  A393X  [LQFP48-AL]
IC22  IRF8313  IRF7103  [SOIC8]
IC23  IRF8313  IRF7103  [SOIC8]
M2  XSM-108-SV  [XSM-108-SV]
M2B  MOLEX11B  [MOLEX11]
R39  100k  R-EU_R0603  [R0603]
R40  150k  R-EU_R0603  [R0603]
R41  47k  R-EU_R0603  [R0603]
R42  10k  R-EU_R0603  [R0603]
R43  10k  R-EU_R0603  [R0603]
R44  0R02  R-EU_R1206  [R1206]

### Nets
+5V: ENC2.1 M2.8 M2B.1 ; also sheet 1,2,3,5,6,8,9,10
DRIVE_MODE: E19.11 ; also sheet 5,6,8,9
DRIVE_RESET: E19.1 ; also sheet 5,6,8,9
GND: C66.2 C67.2 C68.2 C69.2 C72.2 E18.GND(GND:KL) E19.GND(GND:KL) ENC2.3 IC21.17(TEST) IC21.21(CSN) IC21.41(AGND) IC21.TH(PAD) M2.7 M2B.5 R41.1 R42.1 R43.1 R44.1 ; also sheet 1,2,3,4,5,6,8,9,10
M1-HO4: IC21.29(GHB) IC22.2(A:G)
M1-HO5: IC21.26(GHC) IC23.2(A:G)
M1-HO6: IC20.2(A:G) IC21.32(GHA)
M1-LO4: IC21.35(GLB) IC22.4(B:G)
M1-LO5: IC21.34(GLC) IC23.4(B:G)
M1-LO6: IC20.4(B:G) IC21.36(GLA)
M1-VB4: C70.1 IC21.33(CA)
M1-VB5: C71.1 IC21.30(CB)
M1-VB6: C74.1 IC21.27(CC)
M2-A: C70.2 IC20.1(A:S) IC20.5(B:D2) IC20.6(B:D1) IC21.31(SA) M2.2 M2B.8 M2B.9
M2-B: C71.2 IC21.28(SB) IC22.1(A:S) IC22.5(B:D2) IC22.6(B:D1) M2.3 M2B.10 M2B.11
M2-C: C74.2 IC21.25(SC) IC23.1(A:S) IC23.5(B:D2) IC23.6(B:D1) M2.1 M2B.6 M2B.7
M2-COM: IC20.3(B:S) IC21.22(CSP) IC21.38(LSS) IC22.3(B:S) IC23.3(B:S) R44.2
M2_DIR: E19.7 ; also sheet 5
M2_FF1: E19.5 ; also sheet 5
M2_FF2: E19.3 ; also sheet 5
M2_H1: IC21.10(H1) M2.4 M2B.3
M2_H2: IC21.12(H3) M2.5 M2B.4
M2_H3: IC21.11(H2) M2.6 M2B.2
M2_V5: C69.1 IC21.3(V5BD) IC21.4(V5) IC21.8(BRAKE) IC21.39(ESF) IC21.46(COAST) R39.2 R40.2
N$5: E18.8 ENC2.2
N$8: E18.6 ENC2.4
N$105: E19.12 IC21.15(MODE)
N$127: C73.1 IC21.42(CP1)
N$128: C73.2 IC21.43(CP2)
N$130: IC21.18(RDEAD) R42.2
N$131: C72.1 IC21.16(RC) R41.2
N$132: IC21.23(VDSTH) R40.1 R43.2
N$133: IC21.20(REF) R39.1
N$134: C68.1 IC21.40(VREG)
N$141: E19.4 IC21.5(FF2)
N$142: E19.6 IC21.6(FF1)
N$143: E19.10 IC21.14(PWM)
N$144: E19.8 IC21.9(DIR)
N$145: E19.2 IC21.2(RESET)
TIM3_CH1: E18.5 ; also sheet 5
TIM3_CH2: E18.7 ; also sheet 5
TIM5_CH1: E19.9 ; also sheet 5
VCC: C66.1 C67.1 IC20.7(A:D2) IC20.8(A:D1) IC21.24(VDRAIN) IC21.45(VBB) IC22.7(A:D2) IC22.8(A:D1) IC23.7(A:D2) IC23.8(A:D1) ; also sheet 1,2,3,6,8,9,10
Unconnected: IC21.7(TACHO) IC21.19(CSOUT) IC21.44(DIRO)

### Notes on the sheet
- Designer: A.Ryll
- Motor 2

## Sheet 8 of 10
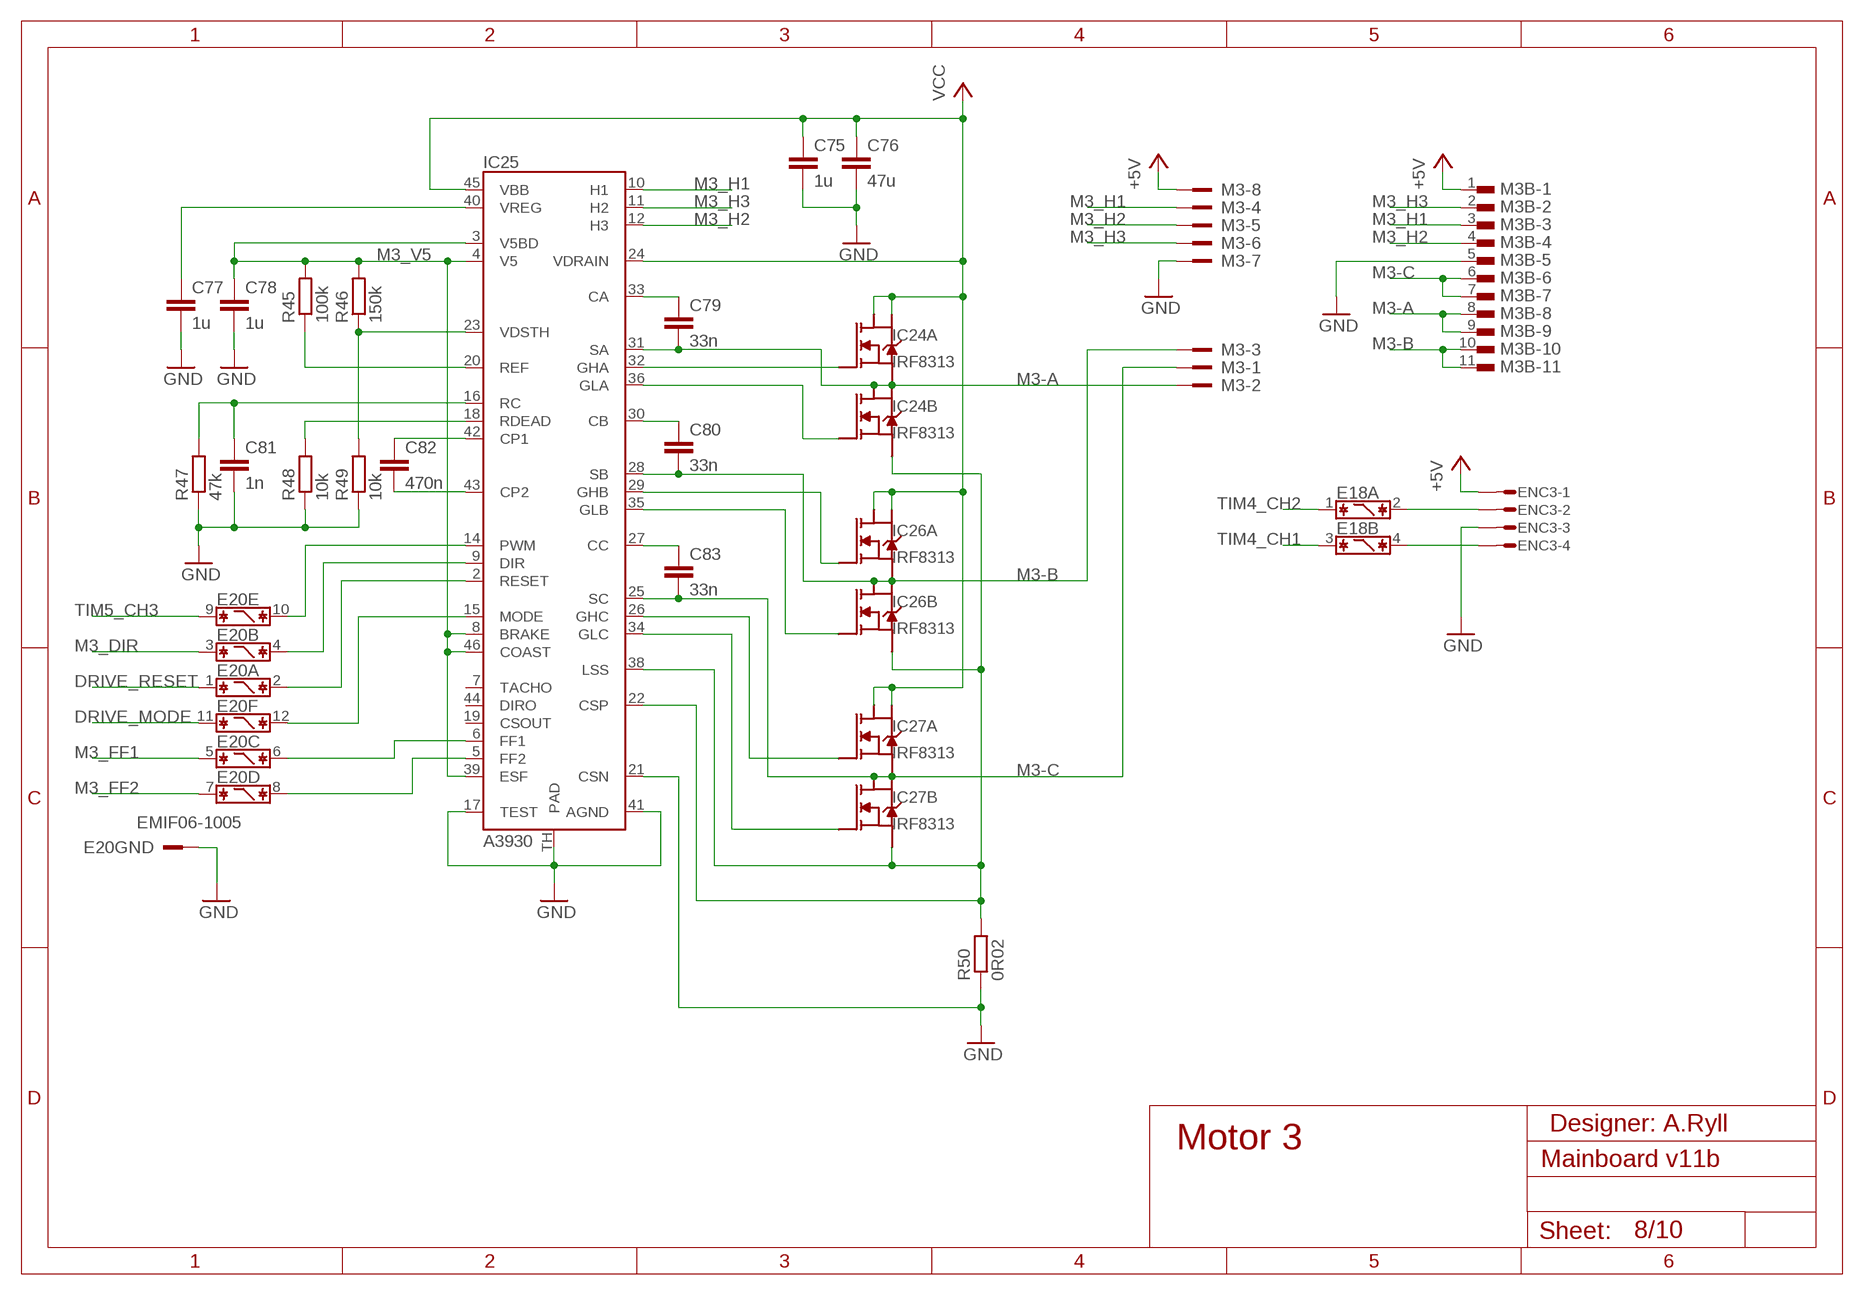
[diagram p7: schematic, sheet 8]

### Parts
C75  1u  C-EUC0603  [C0603]
C76  47u  C-EUC1210  [C1210]
C77  1u  C-EUC0603  [C0603]
C78  1u  C-EUC0603  [C0603]
C79  33n  C-EUC0603  [C0603]
C80  33n  C-EUC0603  [C0603]
C81  1n  C-EUC0603  [C0603]
C82  470n  C-EUC0603  [C0603]
C83  33n  C-EUC0603  [C0603]
E20  EMIF06-1005  [QFN25X15]
ENC3  MICROMATCH-4SMF  [MMT-F-SMD-4]
IC24  IRF8313  IRF7103  [SOIC8]
IC25  A3930  A393X  [LQFP48-AL]
IC26  IRF8313  IRF7103  [SOIC8]
IC27  IRF8313  IRF7103  [SOIC8]
M3  XSM-108-SV  [XSM-108-SV]
M3B  MOLEX11B  [MOLEX11]
R45  100k  R-EU_R0603  [R0603]
R46  150k  R-EU_R0603  [R0603]
R47  47k  R-EU_R0603  [R0603]
R48  10k  R-EU_R0603  [R0603]
R49  10k  R-EU_R0603  [R0603]
R50  0R02  R-EU_R1206  [R1206]

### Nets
+5V: ENC3.1 M3.8 M3B.1 ; also sheet 1,2,3,5,6,7,9,10
DRIVE_MODE: E20.11 ; also sheet 5,6,7,9
DRIVE_RESET: E20.1 ; also sheet 5,6,7,9
GND: C75.2 C76.2 C77.2 C78.2 C81.2 E20.GND(GND:KL) ENC3.3 IC25.17(TEST) IC25.21(CSN) IC25.41(AGND) IC25.TH(PAD) M3.7 M3B.5 R47.1 R48.1 R49.1 R50.1 ; also sheet 1,2,3,4,5,6,7,9,10
M1-HO7: IC25.29(GHB) IC26.2(A:G)
M1-HO8: IC25.26(GHC) IC27.2(A:G)
M1-HO9: IC24.2(A:G) IC25.32(GHA)
M1-LO7: IC25.35(GLB) IC26.4(B:G)
M1-LO8: IC25.34(GLC) IC27.4(B:G)
M1-LO9: IC24.4(B:G) IC25.36(GLA)
M1-VB7: C79.1 IC25.33(CA)
M1-VB8: C80.1 IC25.30(CB)
M1-VB9: C83.1 IC25.27(CC)
M3-A: C79.2 IC24.1(A:S) IC24.5(B:D2) IC24.6(B:D1) IC25.31(SA) M3.2 M3B.8 M3B.9
M3-B: C80.2 IC25.28(SB) IC26.1(A:S) IC26.5(B:D2) IC26.6(B:D1) M3.3 M3B.10 M3B.11
M3-C: C83.2 IC25.25(SC) IC27.1(A:S) IC27.5(B:D2) IC27.6(B:D1) M3.1 M3B.6 M3B.7
M3-COM: IC24.3(B:S) IC25.22(CSP) IC25.38(LSS) IC26.3(B:S) IC27.3(B:S) R50.2
M3_DIR: E20.3 ; also sheet 5
M3_FF1: E20.5 ; also sheet 5
M3_FF2: E20.7 ; also sheet 5
M3_H1: IC25.10(H1) M3.4 M3B.3
M3_H2: IC25.12(H3) M3.5 M3B.4
M3_H3: IC25.11(H2) M3.6 M3B.2
M3_V5: C78.1 IC25.3(V5BD) IC25.4(V5) IC25.8(BRAKE) IC25.39(ESF) IC25.46(COAST) R45.2 R46.2
N$9: E18.2 ENC3.2
N$13: E18.4 ENC3.4
N$50: E20.12 IC25.15(MODE)
N$149: C82.1 IC25.42(CP1)
N$150: C82.2 IC25.43(CP2)
N$152: IC25.18(RDEAD) R48.2
N$153: C81.1 IC25.16(RC) R47.2
N$154: IC25.23(VDSTH) R46.1 R49.2
N$155: IC25.20(REF) R45.1
N$156: C77.1 IC25.40(VREG)
N$163: E20.8 IC25.5(FF2)
N$164: E20.6 IC25.6(FF1)
N$165: E20.10 IC25.14(PWM)
N$166: E20.4 IC25.9(DIR)
N$167: E20.2 IC25.2(RESET)
TIM4_CH1: E18.3 ; also sheet 5
TIM4_CH2: E18.1 ; also sheet 5
TIM5_CH3: E20.9 ; also sheet 5
VCC: C75.1 C76.1 IC24.7(A:D2) IC24.8(A:D1) IC25.24(VDRAIN) IC25.45(VBB) IC26.7(A:D2) IC26.8(A:D1) IC27.7(A:D2) IC27.8(A:D1) ; also sheet 1,2,3,6,7,9,10
Unconnected: IC25.7(TACHO) IC25.19(CSOUT) IC25.44(DIRO)

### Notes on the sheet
- Designer: A.Ryll
- Motor 3

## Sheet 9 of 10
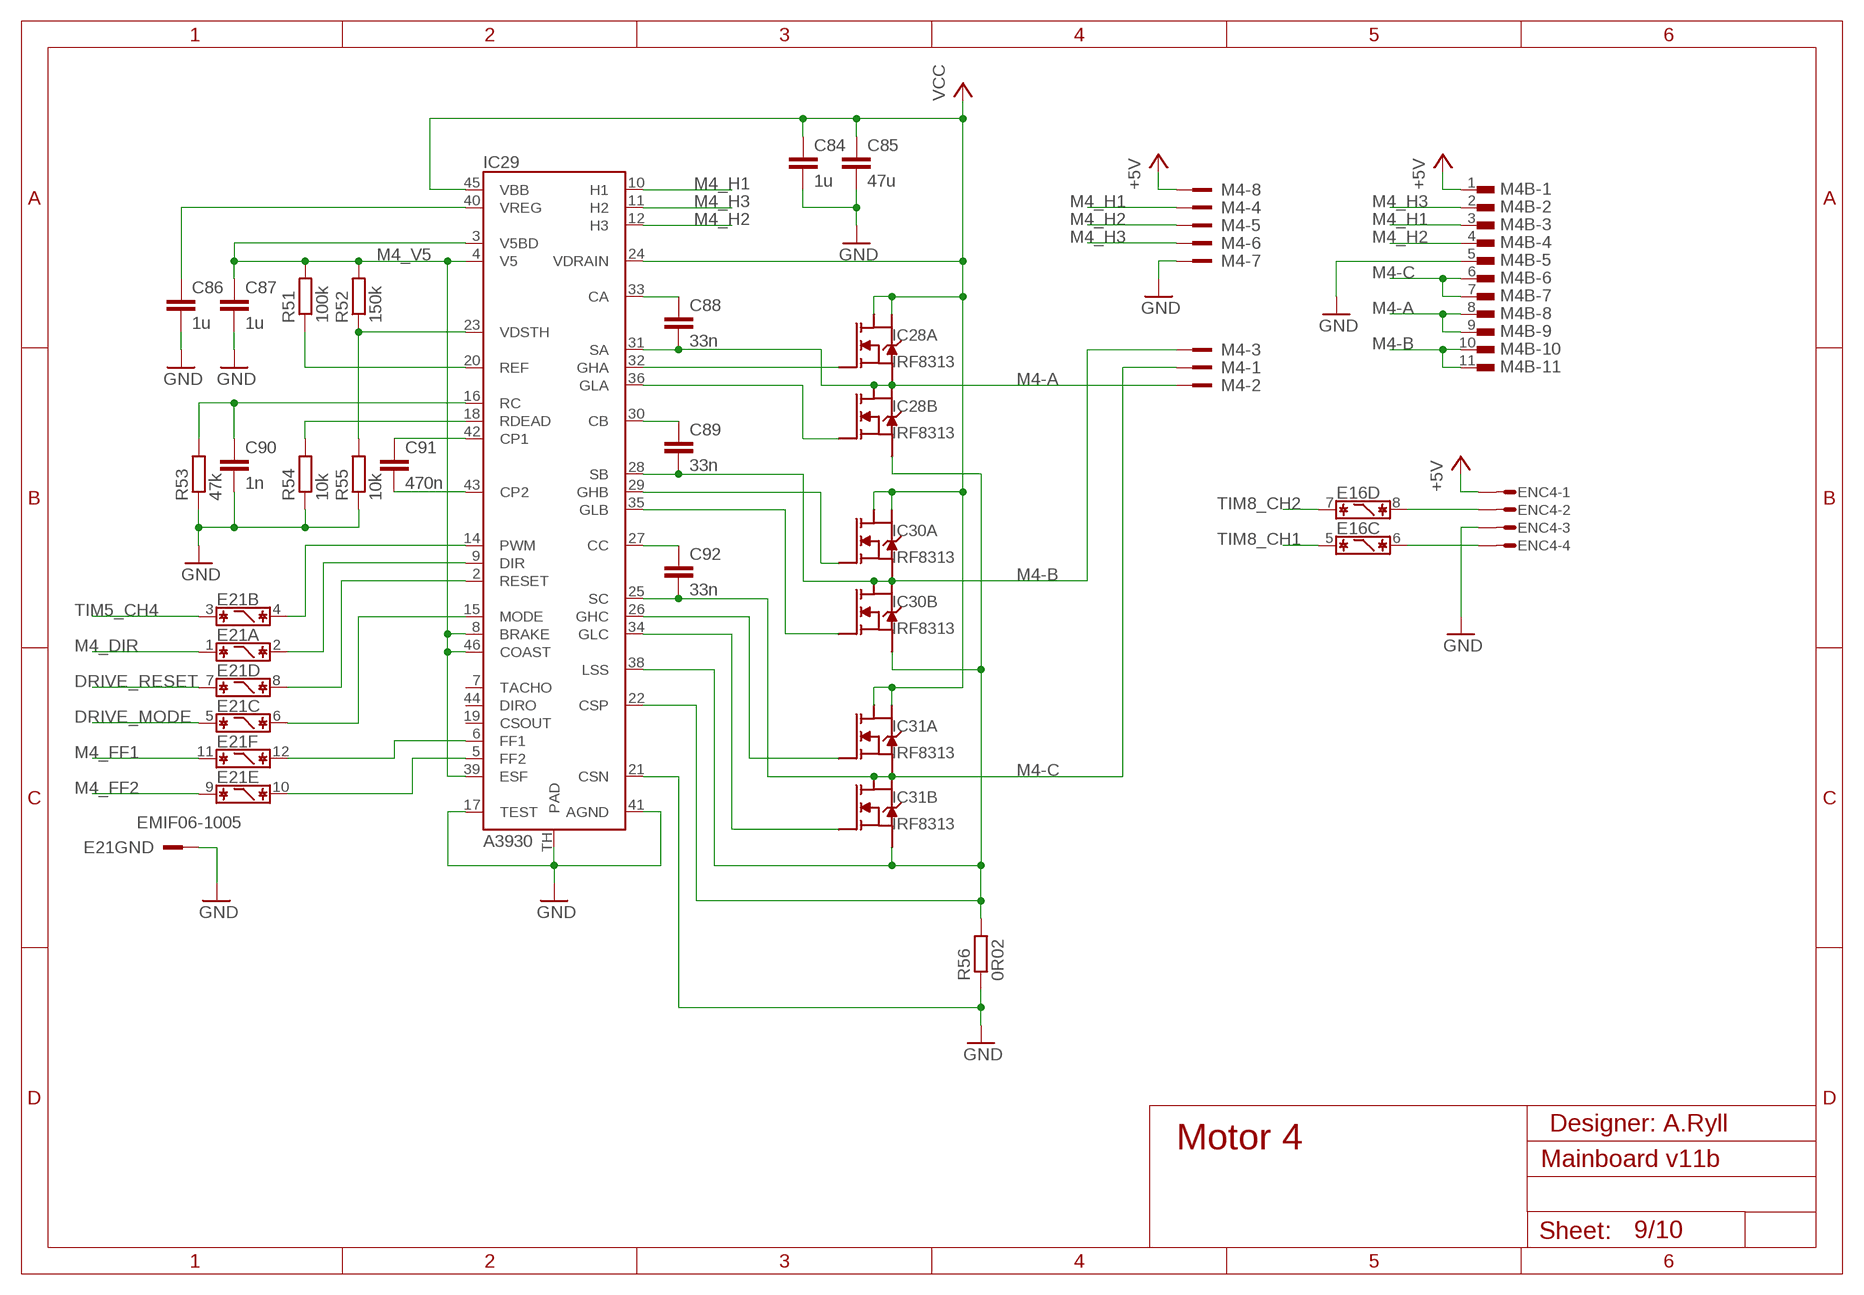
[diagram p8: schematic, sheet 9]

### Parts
C84  1u  C-EUC0603  [C0603]
C85  47u  C-EUC1210  [C1210]
C86  1u  C-EUC0603  [C0603]
C87  1u  C-EUC0603  [C0603]
C88  33n  C-EUC0603  [C0603]
C89  33n  C-EUC0603  [C0603]
C90  1n  C-EUC0603  [C0603]
C91  470n  C-EUC0603  [C0603]
C92  33n  C-EUC0603  [C0603]
E21  EMIF06-1005  [QFN25X15]
ENC4  MICROMATCH-4SMF  [MMT-F-SMD-4]
IC28  IRF8313  IRF7103  [SOIC8]
IC29  A3930  A393X  [LQFP48-AL]
IC30  IRF8313  IRF7103  [SOIC8]
IC31  IRF8313  IRF7103  [SOIC8]
M4  XSM-108-SV  [XSM-108-SV]
M4B  MOLEX11B  [MOLEX11]
R51  100k  R-EU_R0603  [R0603]
R52  150k  R-EU_R0603  [R0603]
R53  47k  R-EU_R0603  [R0603]
R54  10k  R-EU_R0603  [R0603]
R55  10k  R-EU_R0603  [R0603]
R56  0R02  R-EU_R1206  [R1206]

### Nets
+5V: ENC4.1 M4.8 M4B.1 ; also sheet 1,2,3,5,6,7,8,10
DRIVE_MODE: E21.5 ; also sheet 5,6,7,8
DRIVE_RESET: E21.7 ; also sheet 5,6,7,8
GND: C84.2 C85.2 C86.2 C87.2 C90.2 E21.GND(GND:KL) ENC4.3 IC29.17(TEST) IC29.21(CSN) IC29.41(AGND) IC29.TH(PAD) M4.7 M4B.5 R53.1 R54.1 R55.1 R56.1 ; also sheet 1,2,3,4,5,6,7,8,10
M1-HO10: IC29.29(GHB) IC30.2(A:G)
M1-HO11: IC29.26(GHC) IC31.2(A:G)
M1-HO12: IC28.2(A:G) IC29.32(GHA)
M1-LO10: IC29.35(GLB) IC30.4(B:G)
M1-LO11: IC29.34(GLC) IC31.4(B:G)
M1-LO12: IC28.4(B:G) IC29.36(GLA)
M1-VB10: C88.1 IC29.33(CA)
M1-VB11: C89.1 IC29.30(CB)
M1-VB12: C92.1 IC29.27(CC)
M4-A: C88.2 IC28.1(A:S) IC28.5(B:D2) IC28.6(B:D1) IC29.31(SA) M4.2 M4B.8 M4B.9
M4-B: C89.2 IC29.28(SB) IC30.1(A:S) IC30.5(B:D2) IC30.6(B:D1) M4.3 M4B.10 M4B.11
M4-C: C92.2 IC29.25(SC) IC31.1(A:S) IC31.5(B:D2) IC31.6(B:D1) M4.1 M4B.6 M4B.7
M4-COM: IC28.3(B:S) IC29.22(CSP) IC29.38(LSS) IC30.3(B:S) IC31.3(B:S) R56.2
M4_DIR: E21.1 ; also sheet 5
M4_FF1: E21.11 ; also sheet 5
M4_FF2: E21.9 ; also sheet 5
M4_H1: IC29.10(H1) M4.4 M4B.3
M4_H2: IC29.12(H3) M4.5 M4B.4
M4_H3: IC29.11(H2) M4.6 M4B.2
M4_V5: C87.1 IC29.3(V5BD) IC29.4(V5) IC29.8(BRAKE) IC29.39(ESF) IC29.46(COAST) R51.2 R52.2
N$34: E21.6 IC29.15(MODE)
N$89: E16.8 ENC4.2
N$94: E16.6 ENC4.4
N$171: C91.1 IC29.42(CP1)
N$172: C91.2 IC29.43(CP2)
N$174: IC29.18(RDEAD) R54.2
N$175: C90.1 IC29.16(RC) R53.2
N$176: IC29.23(VDSTH) R52.1 R55.2
N$177: IC29.20(REF) R51.1
N$178: C86.1 IC29.40(VREG)
N$185: E21.10 IC29.5(FF2)
N$186: E21.12 IC29.6(FF1)
N$187: E21.4 IC29.14(PWM)
N$188: E21.2 IC29.9(DIR)
N$189: E21.8 IC29.2(RESET)
TIM5_CH4: E21.3 ; also sheet 5
TIM8_CH1: E16.5 ; also sheet 5
TIM8_CH2: E16.7 ; also sheet 5
VCC: C84.1 C85.1 IC28.7(A:D2) IC28.8(A:D1) IC29.24(VDRAIN) IC29.45(VBB) IC30.7(A:D2) IC30.8(A:D1) IC31.7(A:D2) IC31.8(A:D1) ; also sheet 1,2,3,6,7,8,10
Unconnected: IC29.7(TACHO) IC29.19(CSOUT) IC29.44(DIRO)

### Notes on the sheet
- Designer: A.Ryll
- Motor 4

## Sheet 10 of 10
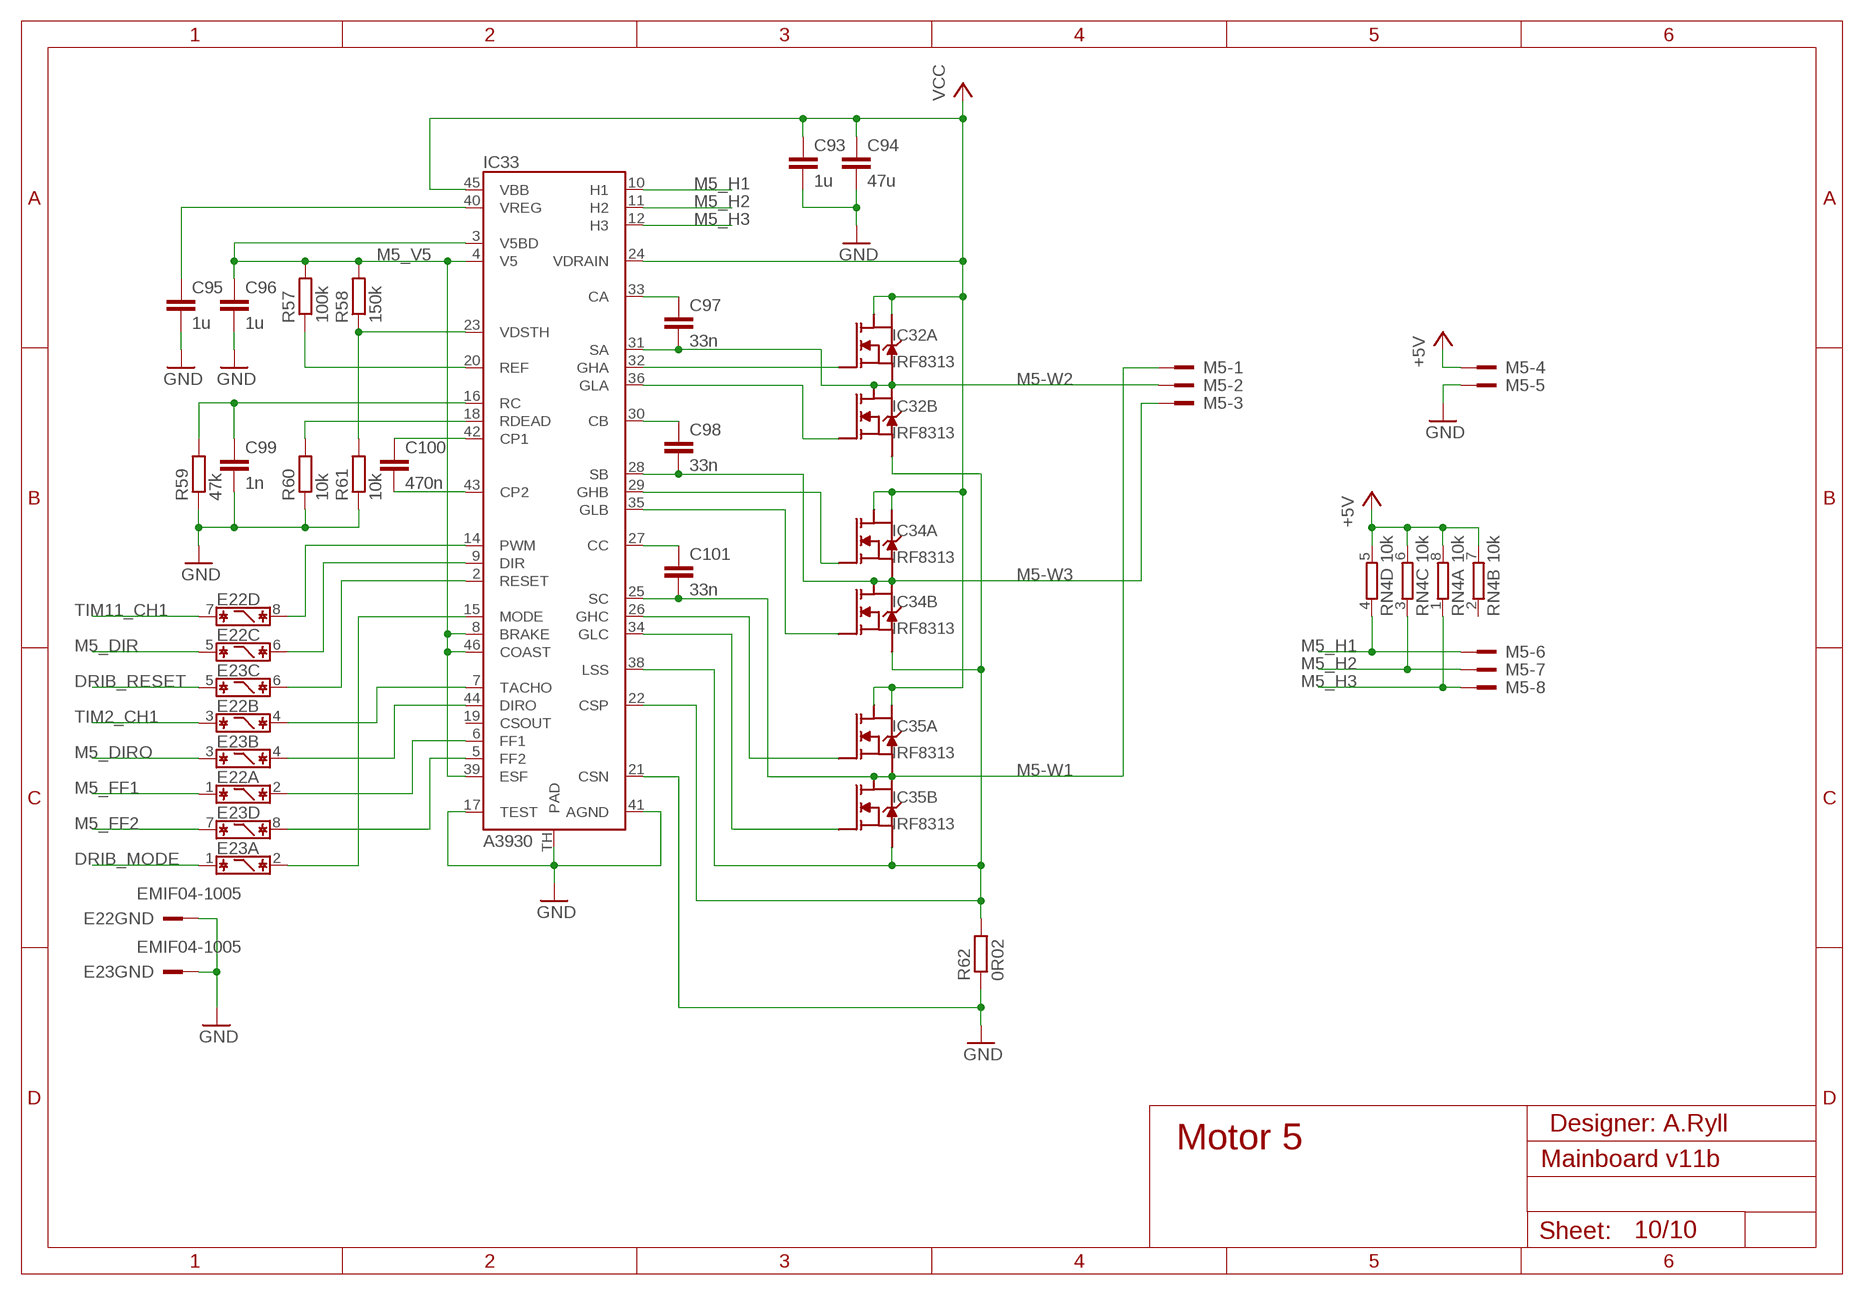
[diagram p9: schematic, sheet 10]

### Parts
C93  1u  C-EUC0603  [C0603]
C94  47u  C-EUC1210  [C1210]
C95  1u  C-EUC0603  [C0603]
C96  1u  C-EUC0603  [C0603]
C97  33n  C-EUC0603  [C0603]
C98  33n  C-EUC0603  [C0603]
C99  1n  C-EUC0603  [C0603]
C100  470n  C-EUC0603  [C0603]
C101  33n  C-EUC0603  [C0603]
E22  EMIF04-1005  [QFN17X15]
E23  EMIF04-1005  [QFN17X15]
IC32  IRF8313  IRF7103  [SOIC8]
IC33  A3930  A393X  [LQFP48-AL]
IC34  IRF8313  IRF7103  [SOIC8]
IC35  IRF8313  IRF7103  [SOIC8]
M5  XSM-108-SV  [XSM-108-SV]
R57  100k  R-EU_R0603  [R0603]
R58  150k  R-EU_R0603  [R0603]
R59  47k  R-EU_R0603  [R0603]
R60  10k  R-EU_R0603  [R0603]
R61  10k  R-EU_R0603  [R0603]
R62  0R02  R-EU_R1206  [R1206]
RN4  10k  4R-NEXB28V  [EXB28V]

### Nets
+5V: M5.4 RN4.5 RN4.6 RN4.7 RN4.8 ; also sheet 1,2,3,5,6,7,8,9
DRIB_MODE: E23.1 ; also sheet 5
DRIB_RESET: E23.5 ; also sheet 5
GND: C93.2 C94.2 C95.2 C96.2 C99.2 E22.GND(GND:KL) E23.GND(GND:KL) IC33.17(TEST) IC33.21(CSN) IC33.41(AGND) IC33.TH(PAD) M5.5 R59.1 R60.1 R61.1 R62.1 ; also sheet 1,2,3,4,5,6,7,8,9
M1-HO13: IC33.29(GHB) IC34.2(A:G)
M1-HO14: IC33.26(GHC) IC35.2(A:G)
M1-HO15: IC32.2(A:G) IC33.32(GHA)
M1-LO13: IC33.35(GLB) IC34.4(B:G)
M1-LO14: IC33.34(GLC) IC35.4(B:G)
M1-LO15: IC32.4(B:G) IC33.36(GLA)
M1-VB13: C97.1 IC33.33(CA)
M1-VB14: C98.1 IC33.30(CB)
M1-VB15: C101.1 IC33.27(CC)
M5-COM: IC32.3(B:S) IC33.22(CSP) IC33.38(LSS) IC34.3(B:S) IC35.3(B:S) R62.2
M5-W1: C101.2 IC33.25(SC) IC35.1(A:S) IC35.5(B:D2) IC35.6(B:D1) M5.1
M5-W2: C97.2 IC32.1(A:S) IC32.5(B:D2) IC32.6(B:D1) IC33.31(SA) M5.2
M5-W3: C98.2 IC33.28(SB) IC34.1(A:S) IC34.5(B:D2) IC34.6(B:D1) M5.3
M5_DIR: E22.5 ; also sheet 5
M5_DIRO: E23.3 ; also sheet 5
M5_FF1: E22.1 ; also sheet 5
M5_FF2: E23.7 ; also sheet 5
M5_H1: IC33.10(H1) M5.6 RN4.4
M5_H2: IC33.11(H2) M5.7 RN4.3
M5_H3: IC33.12(H3) M5.8 RN4.1
M5_V5: C96.1 IC33.3(V5BD) IC33.4(V5) IC33.8(BRAKE) IC33.39(ESF) IC33.46(COAST) R57.2 R58.2
N$12: E23.2 IC33.15(MODE)
N$191: E23.4 IC33.44(DIRO)
N$193: C100.1 IC33.42(CP1)
N$194: C100.2 IC33.43(CP2)
N$196: IC33.18(RDEAD) R60.2
N$197: C99.1 IC33.16(RC) R59.2
N$198: IC33.23(VDSTH) R58.1 R61.2
N$199: IC33.20(REF) R57.1
N$200: C95.1 IC33.40(VREG)
N$207: E23.8 IC33.5(FF2)
N$208: E22.2 IC33.6(FF1)
N$209: E22.8 IC33.14(PWM)
N$210: E22.6 IC33.9(DIR)
N$211: E23.6 IC33.2(RESET)
N$213: E22.4 IC33.7(TACHO)
TIM2_CH1: E22.3 ; also sheet 5
TIM11_CH1: E22.7 ; also sheet 5
VCC: C93.1 C94.1 IC32.7(A:D2) IC32.8(A:D1) IC33.24(VDRAIN) IC33.45(VBB) IC34.7(A:D2) IC34.8(A:D1) IC35.7(A:D2) IC35.8(A:D1) ; also sheet 1,2,3,6,7,8,9
Unconnected: IC33.19(CSOUT) RN4.2

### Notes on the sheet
- Designer: A.Ryll
- Motor 5

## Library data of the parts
BAT+ BAT- = Marvin:WIREPAD: Wire PAD connect wire on PCB
C1-C101 = rcl:C-EU: CAPACITOR, European symbol
D1 = diode:DIODE-: DIODE
DISPLAY = Marvin:LT24: Terasic LT24 Display Board Header: TSM-120-01-T-DV-P
E1-E10 E12-E14 E16 E18 E22 E23 = Marvin:EMIF04-1005
E11 E15 E17 E19-E21 = Marvin:EMIF06-1005
ENC1-ENC4 = con-amp-micromatch:MICROMATCH-4: MicroMaTch 4 7-215464-4 / 0-215464-4 Drawing Number C-215464 DDEController.pdf
EXT = Marvin:XSM-106-DV
IC1 = Marvin:INA21X
IC2 = Marvin:LTC4231: Micropower Hot Swap Controller
IC3 = Marvin:LTC2955: Pushbutton On/Off Controller with Automatic Turn-On
IC4 = Marvin:LT3080ST
IC5 = Marvin:ST1S40IP
IC6 = Marvin:AD-OP1
IC7 = Marvin:ADC__4S__1
IC8 IC10 = Marvin:STMPS21
IC9 = Marvin:FLASH: Micron Flash Chip
IC11 = Marvin:MPU-6000: InvenSense MPU-6000 Gyroscope + Accelerometer
IC12 = linear:MCP1703: 250 mA, 16V, Low Quiescent Current LDO Regulator Source: http://ww1.microchip.com/downloads/en/DeviceDoc/22049b.pdf
IC13 = microchip:93*: Serial EPROM 1 K/2 K/4 K, low voltage, Microwire; MF: MICROCHIP; MPN: 93LC66/SN; OC_FARNELL: 1296586; OC_NEWARK: 65K1154
IC14 = Marvin:FT2232H
IC15 = Marvin:STM32F74_Z: STM32F74xZx 216 MHz, 320KB RAM, 1024 KB Flash
IC16 IC18-IC20 IC22-IC24 IC26-IC28 IC30-IC32 IC34 IC35 = Marvin:IRF7103
IC17 IC21 IC25 IC29 IC33 = Marvin:A393X
INT = testpad:TP: Test pad
IR1 IR2 = con-hirose-df13:DF13-3P-1.25: DF13-3P 1.25mm Pitch Miniature Crimping Connector.
KD = con-amp-micromatch:MICROMATCH-16: MicroMaTch 16 8-215464-6 / 1-215464-6 Drawing Number C-215464 DDEController.pdf
L1 L4-L13 = wuerth-elektronik:WE-CBF: SMD EMI Suppression Ferrite Beads
L2 = Marvin:L
L3 L14 L15 = wuerth-elektronik:WE-MI: SMD Multilayer Inductor WE-MI
LED1 = led:LED: LED
LED2 LED3 = led:DUOLED5MM: DUO LED 2 colors, 5 mm, round
M1-M5 = Marvin:XSM-108-SV
M1B M2B M3B M4B = Marvin:MOLEX11
MSL MSR = con-hirose-df13:DF13-6P-1.25: DF13-6P 1.25mm Pitch Miniature Crimping Connector.
NRF24 = Marvin:NRFL01MOD
PWR RESET = Marvin:KT11
Q1 = Marvin:NMOS4D
Q2 Q8-Q11 = transistor-small-signal:BSS84: P-CHANNEL MOS FET
Q3-Q5 = transistor-small-signal:BSS123: N-CHANNEL MOS FET
Q6 Q7 = Marvin:OSCI
R1-R62 = rcl:R-EU_: RESISTOR, European symbol
RN1-RN4 = resistor-dil:4R-N: Array Chip Resistor Source: RS Component / Phycomp; OC_FARNELL: unknown; OC_NEWARK: unknown
SD = Marvin:SDCARD: TE Connectivity 2041021-3 SD Card Socket Farnell Order Number: 2112526
SG1 = Marvin:BUZZER
USB = Marvin:USBA: Multicomp connector Farnell: 2112370
USB1 = Marvin:USB-B: USB Connector Micro: Molex 47346-0001

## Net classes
0 default: width 0.152 mm, clearance 0.152 mm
